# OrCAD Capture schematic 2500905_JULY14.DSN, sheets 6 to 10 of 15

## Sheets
6 PAGE10: size Custom
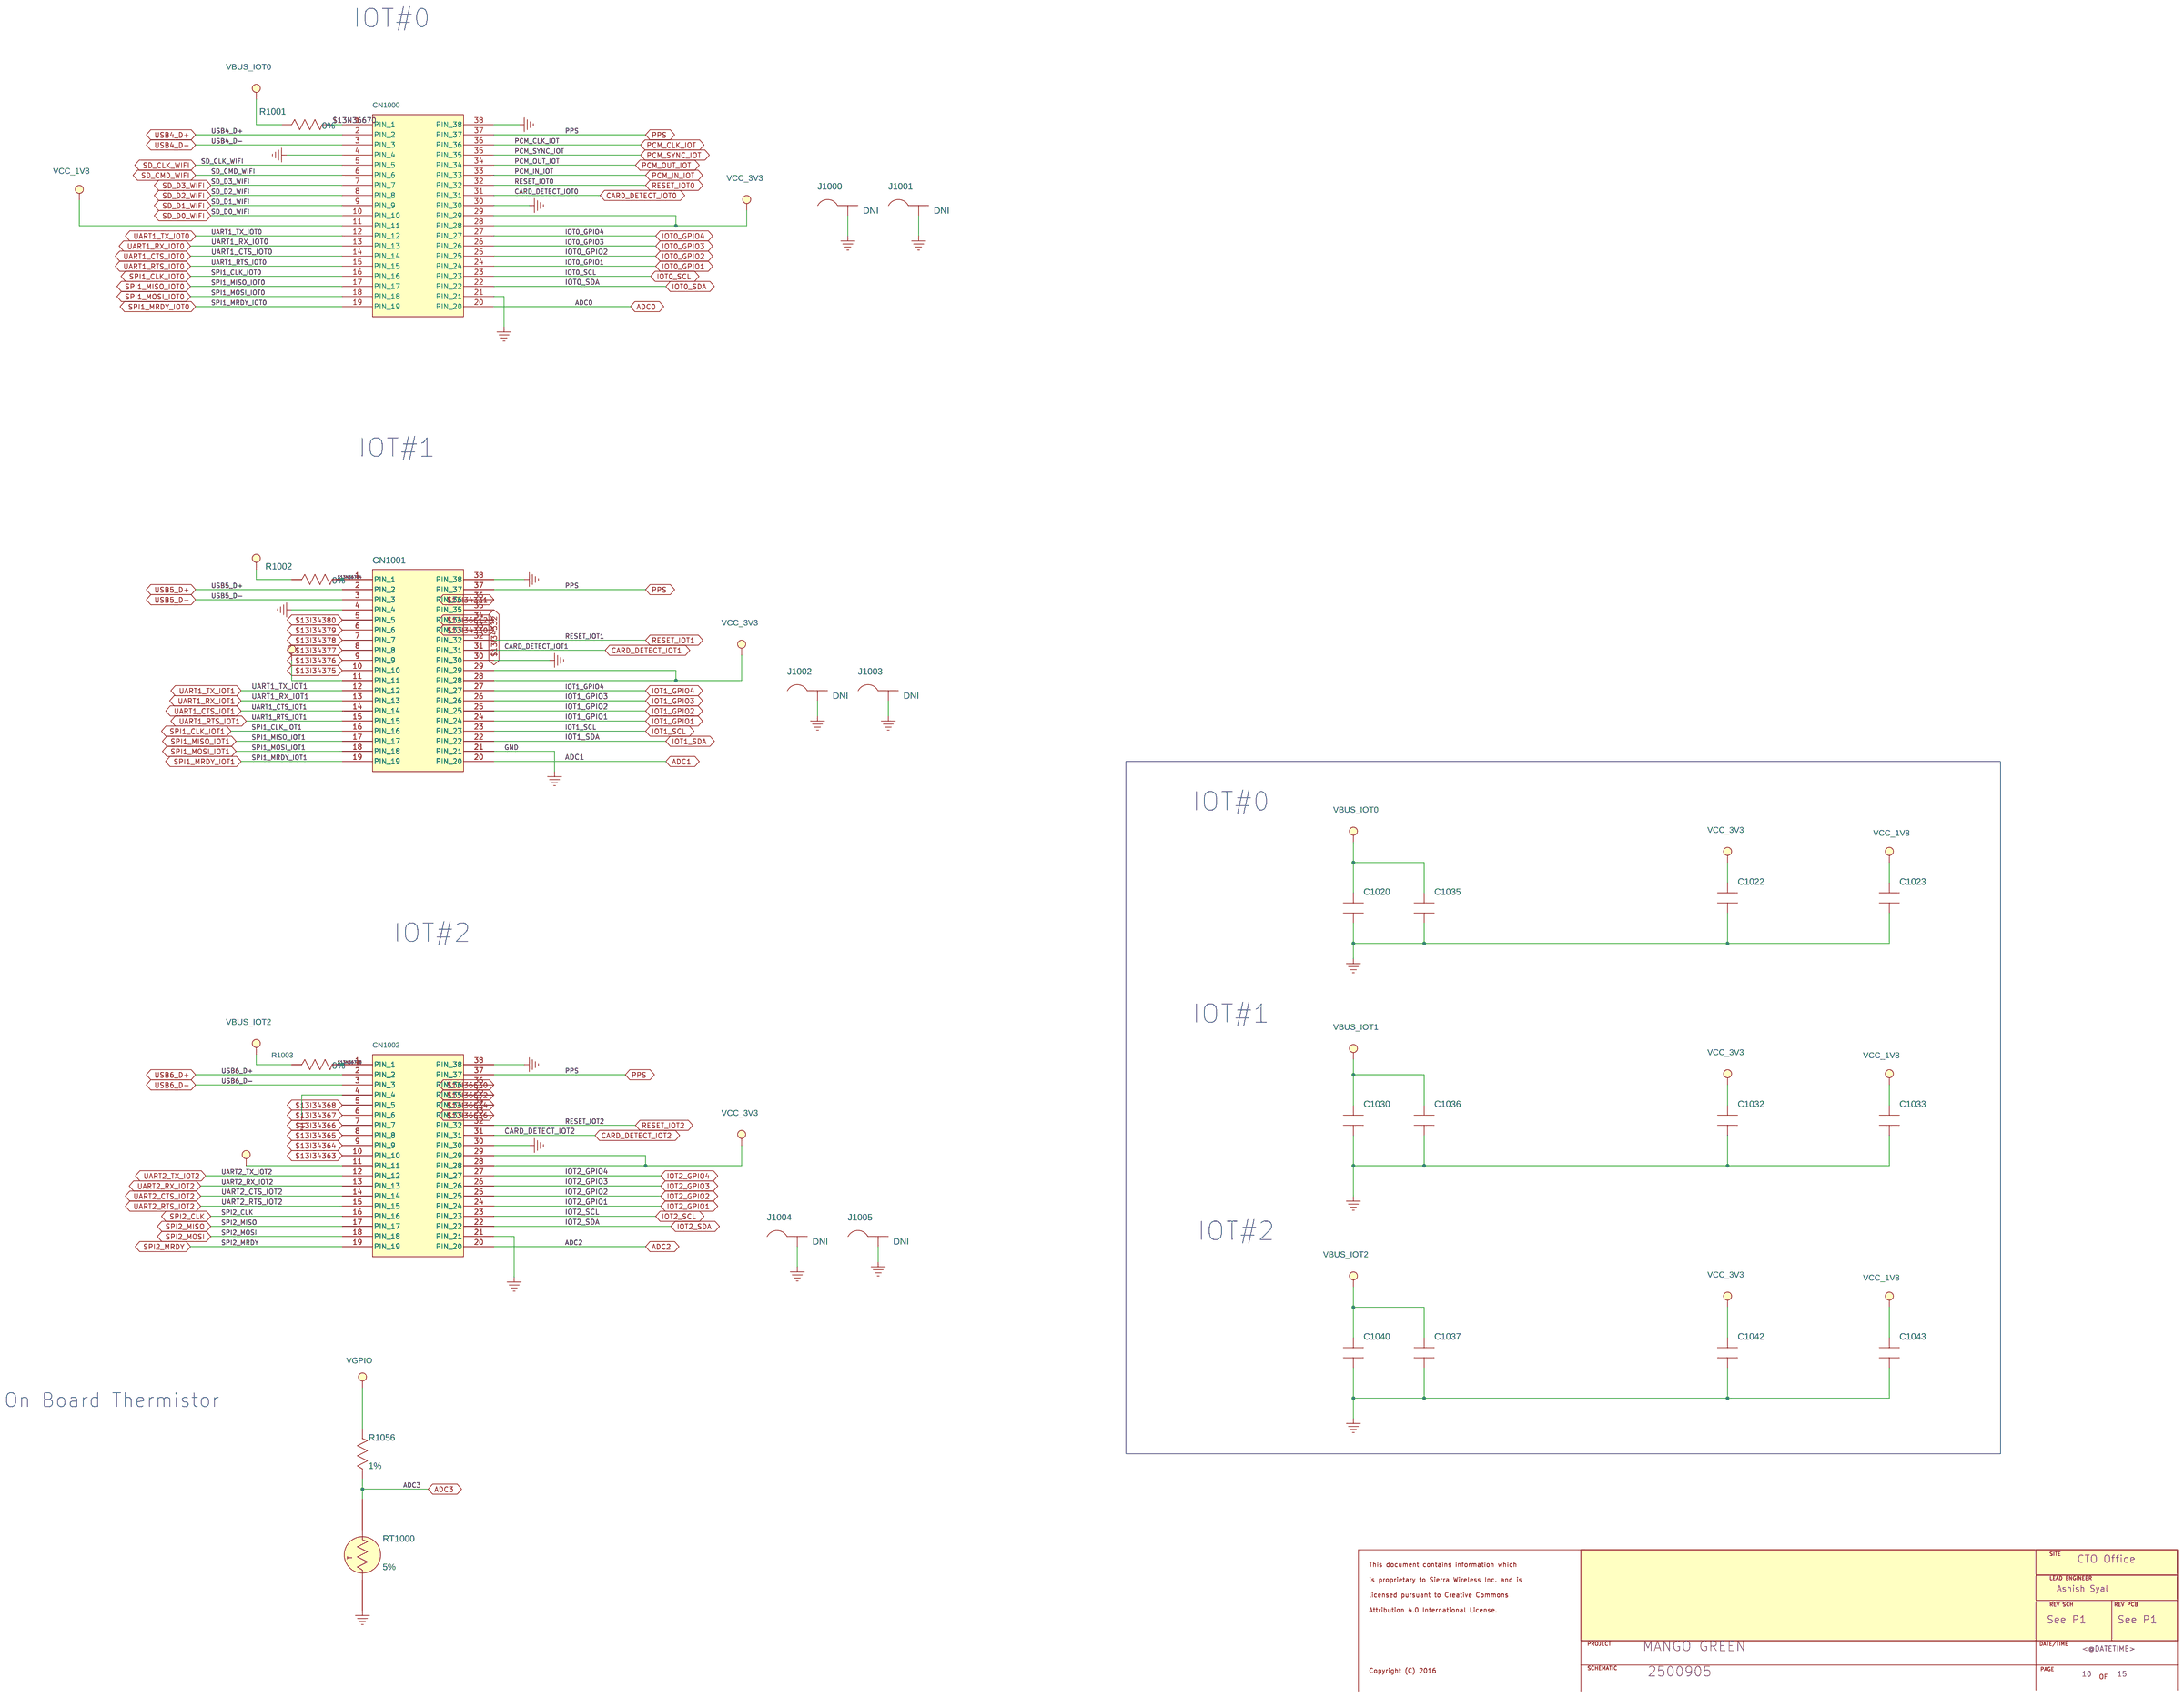
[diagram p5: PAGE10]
7 PAGE9: size Custom
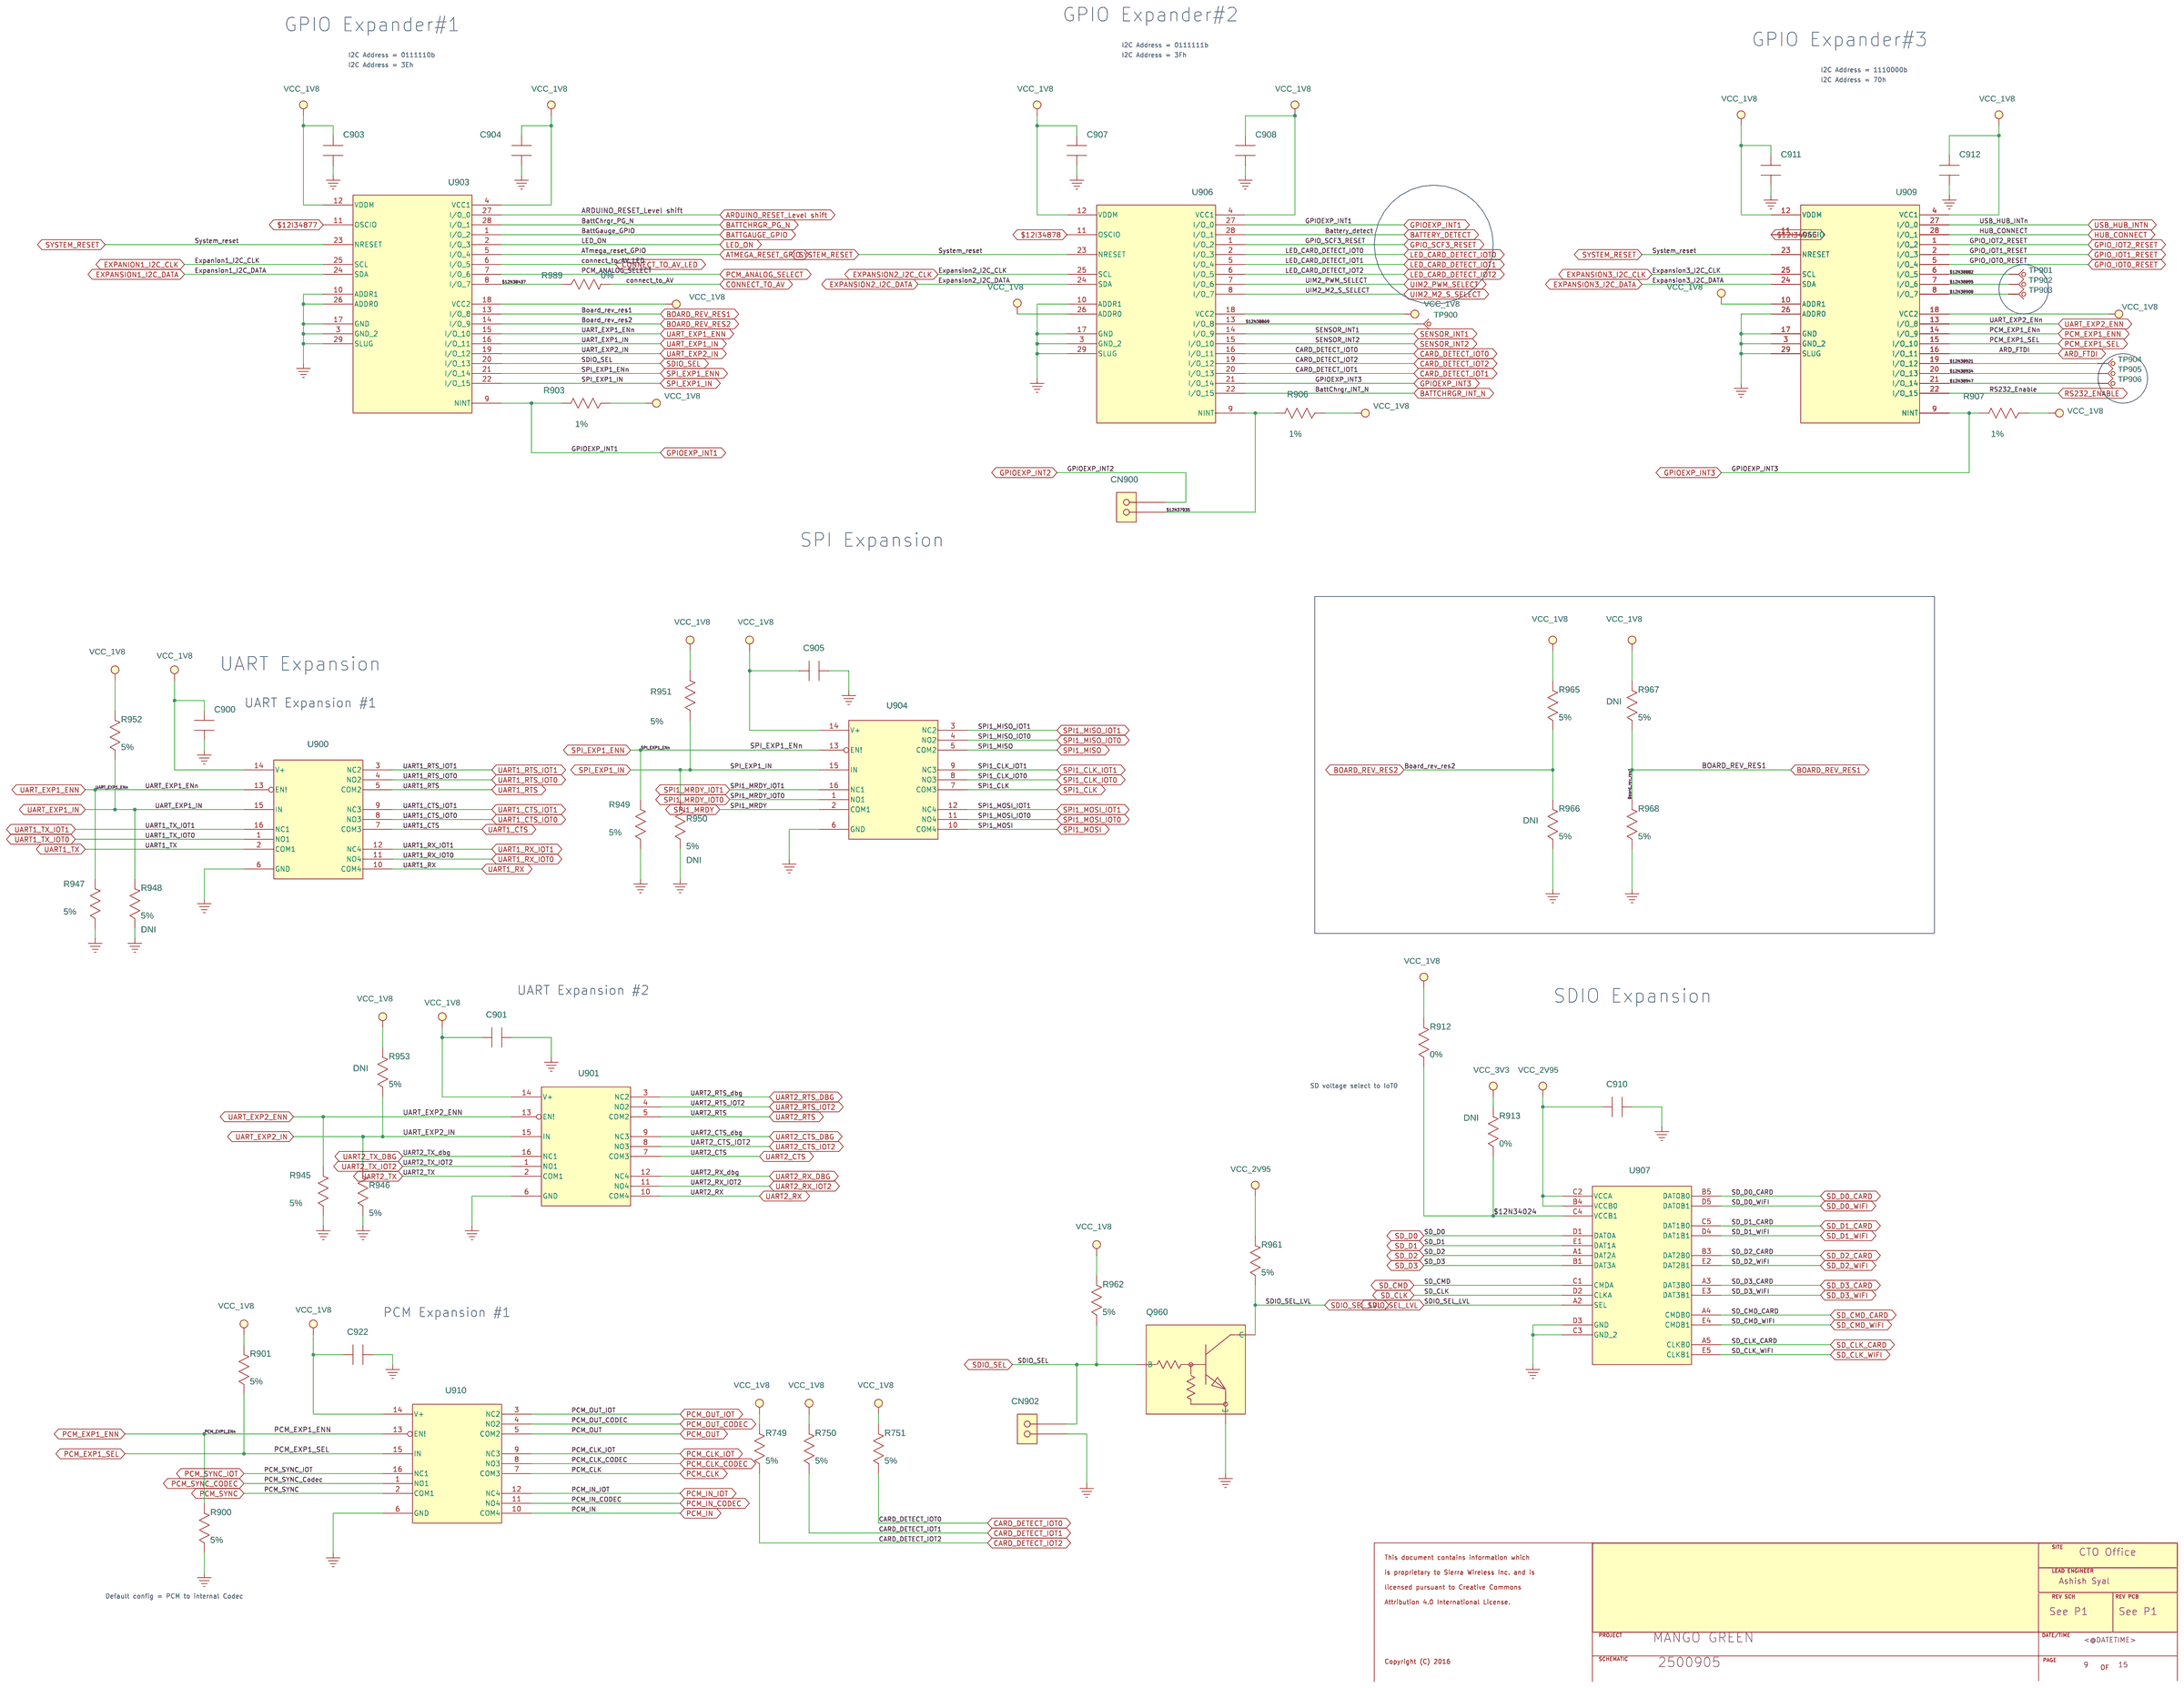
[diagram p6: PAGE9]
8 PAGE8: size Custom
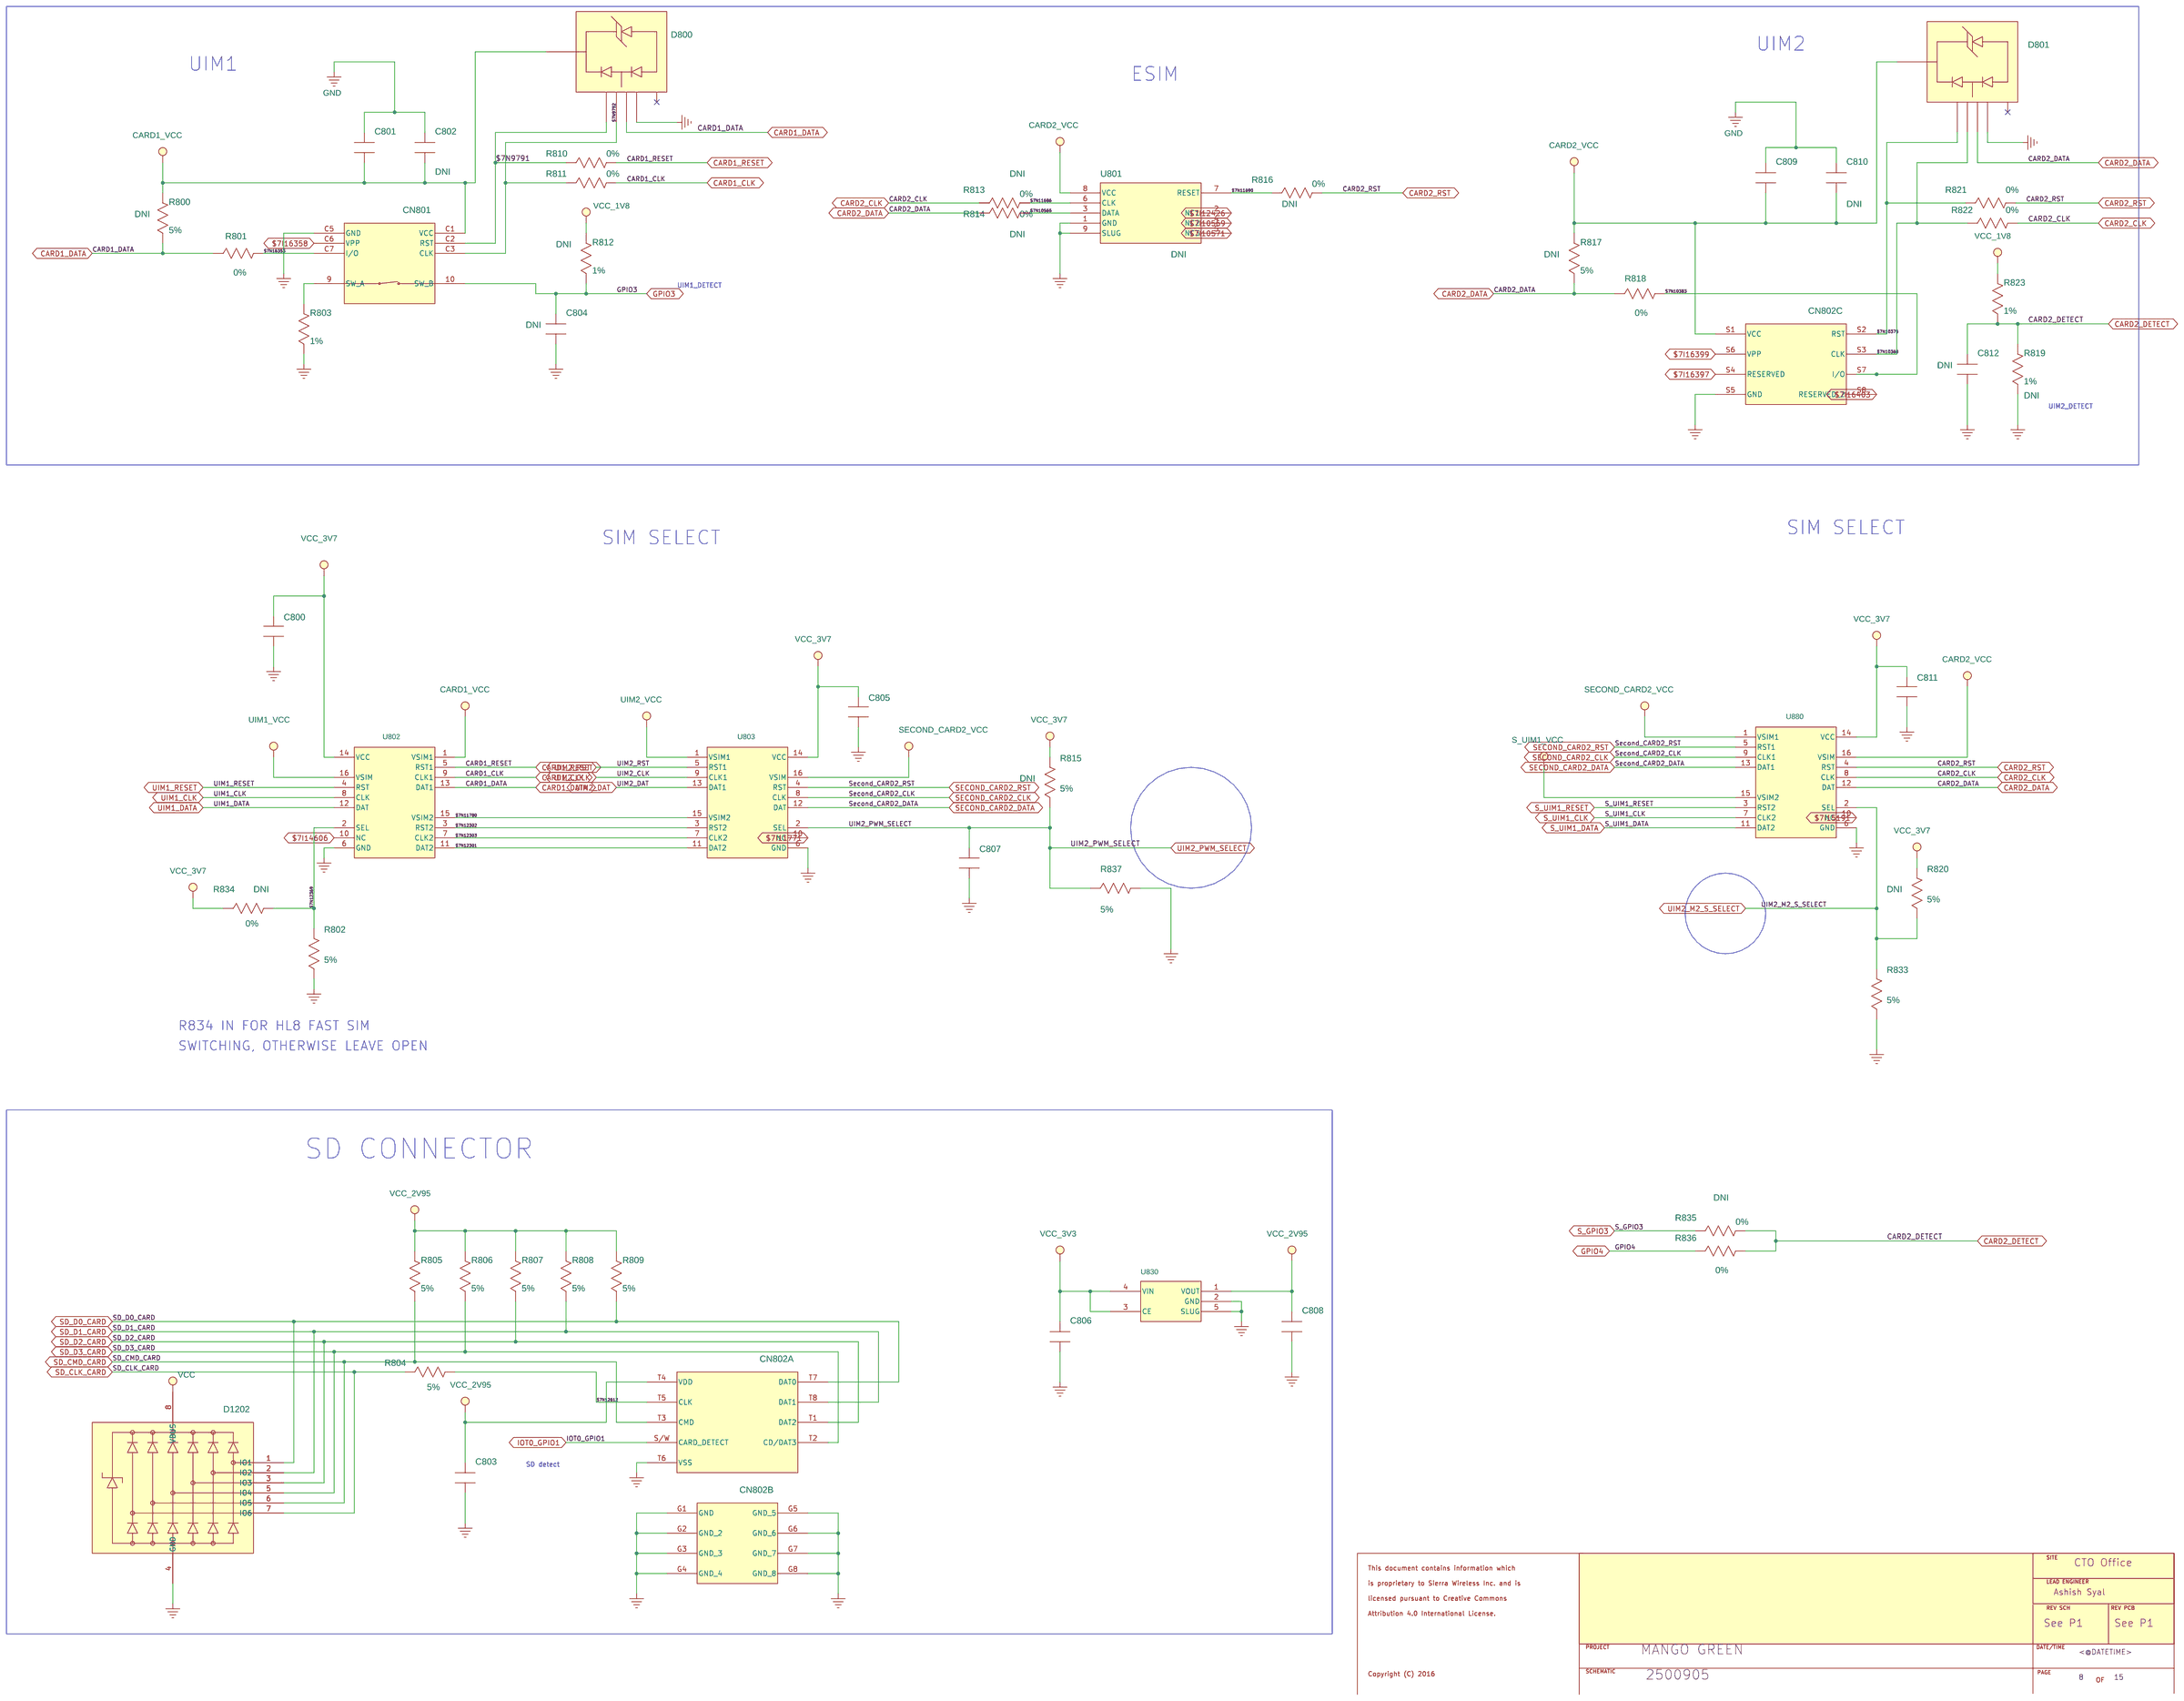
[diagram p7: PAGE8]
9 PAGE7: size Custom
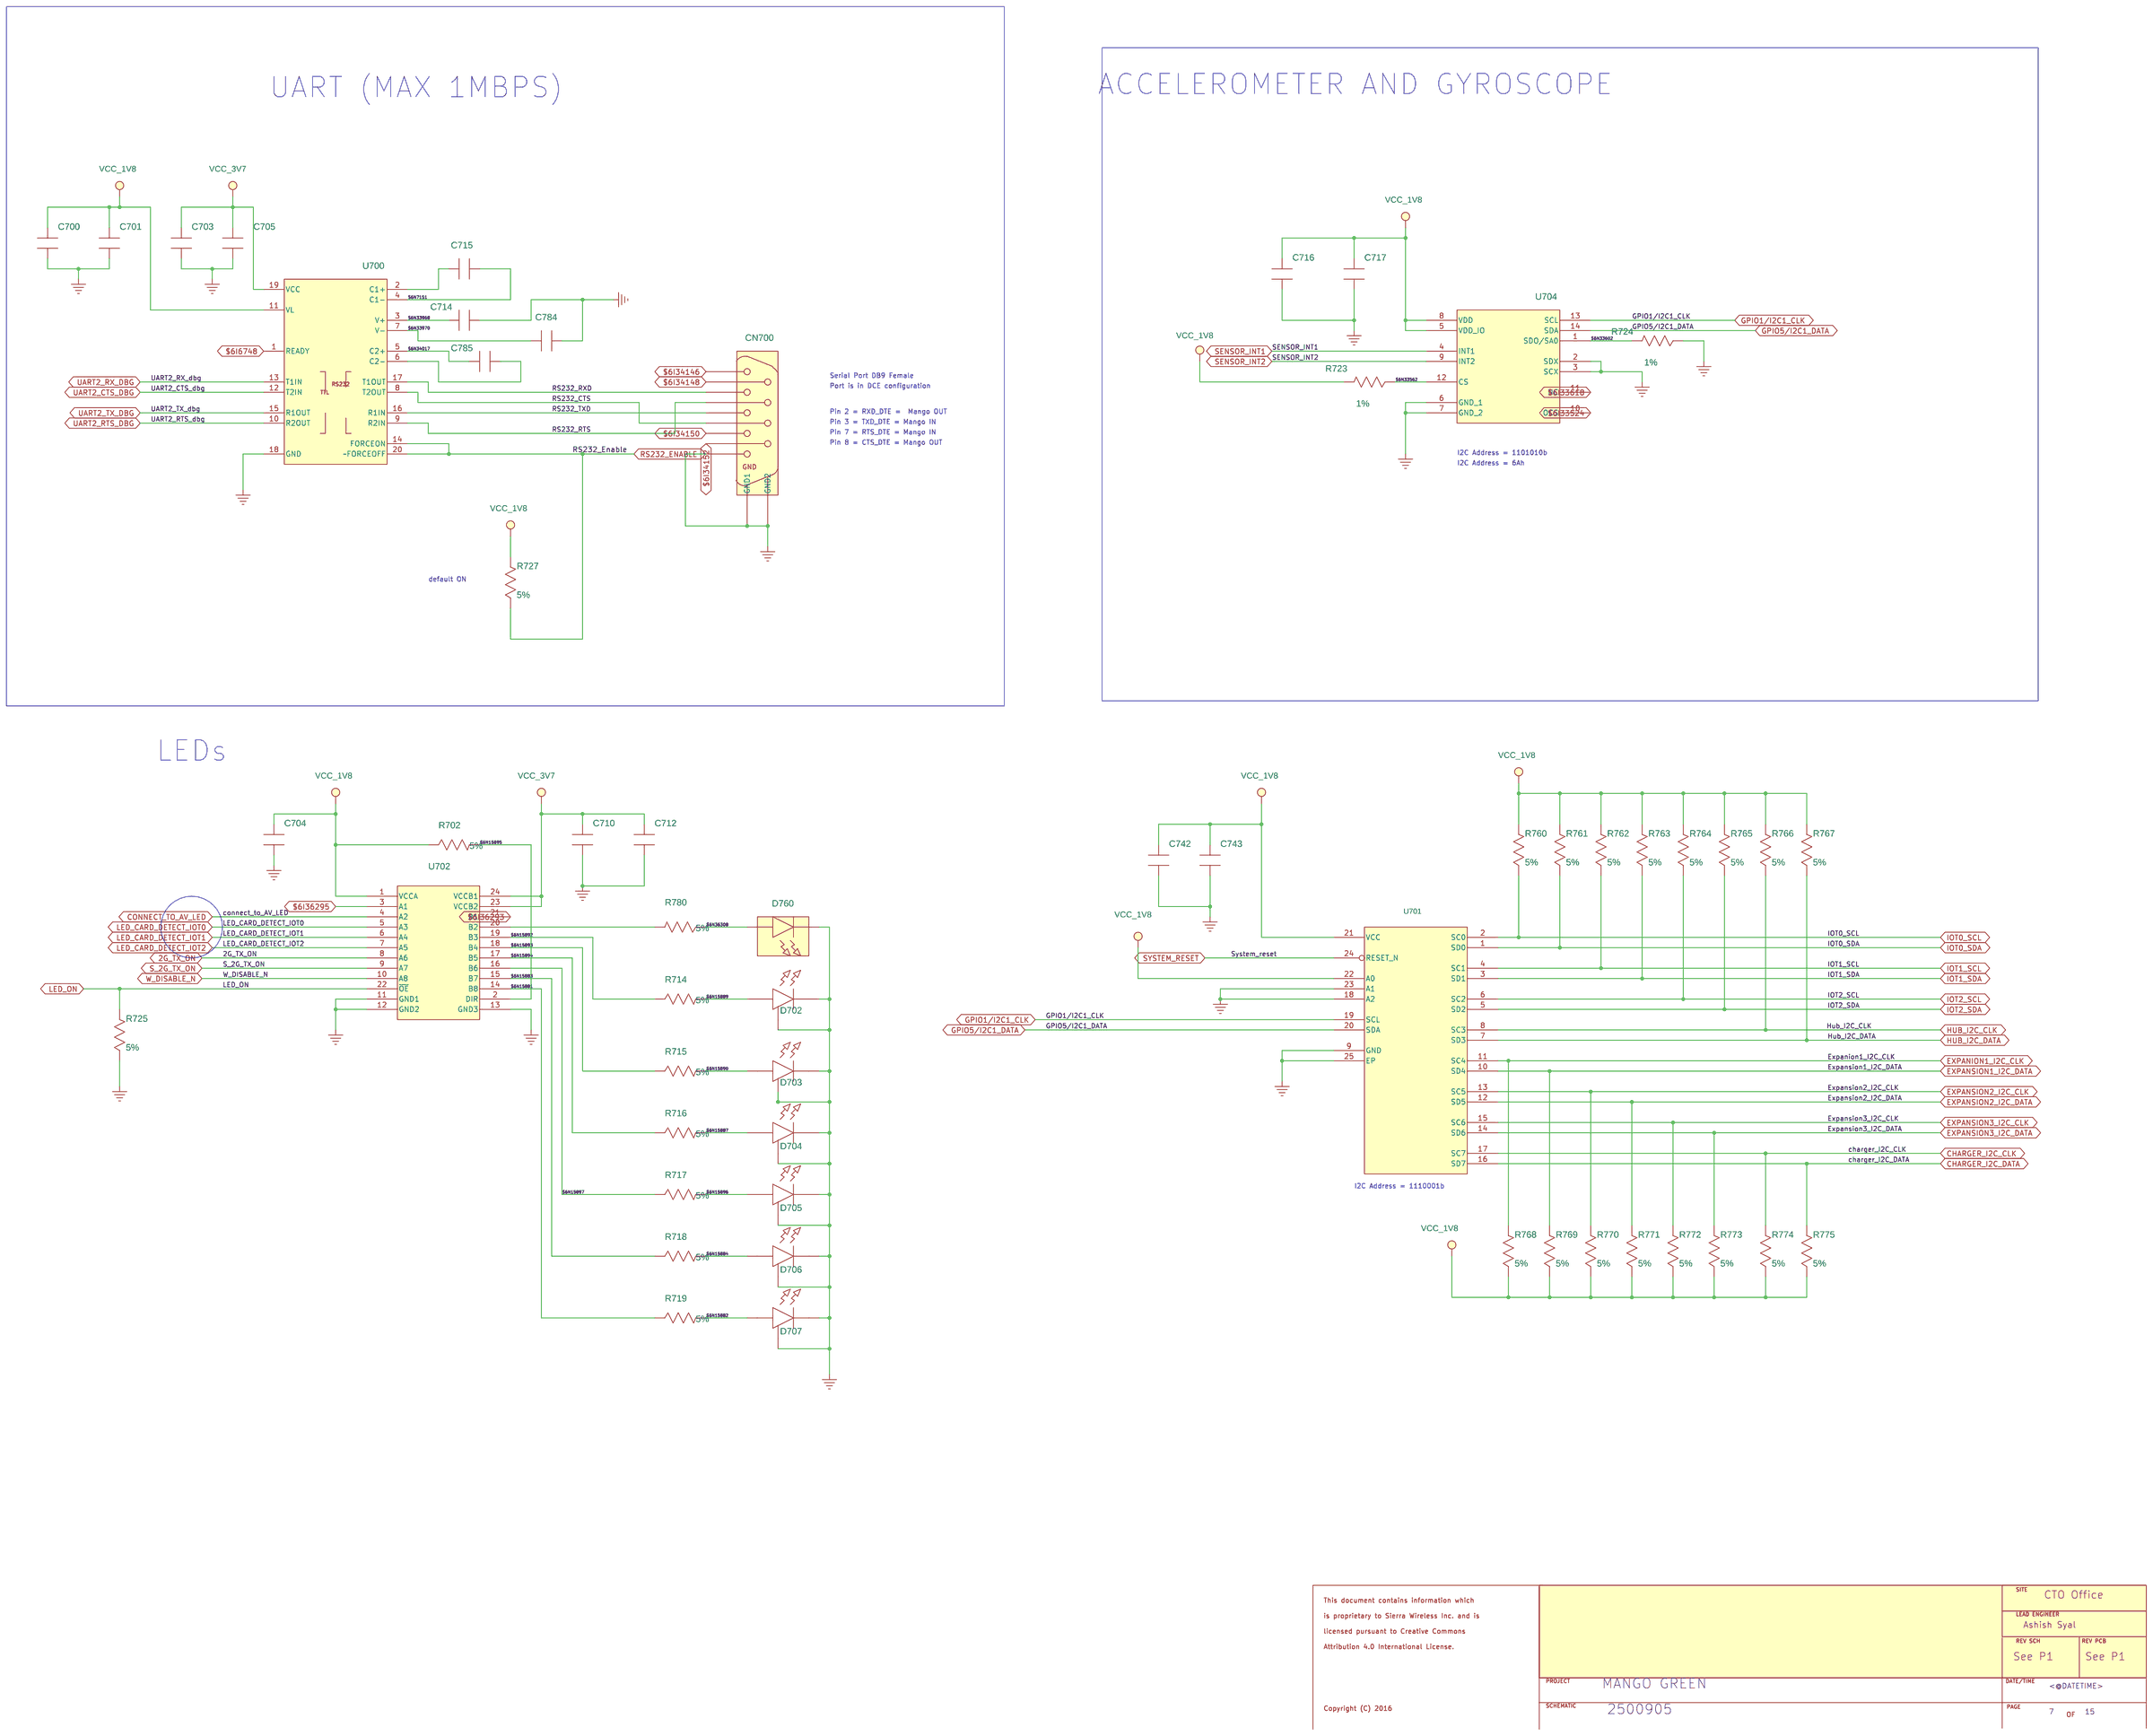
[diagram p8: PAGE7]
10 PAGE6: size Custom
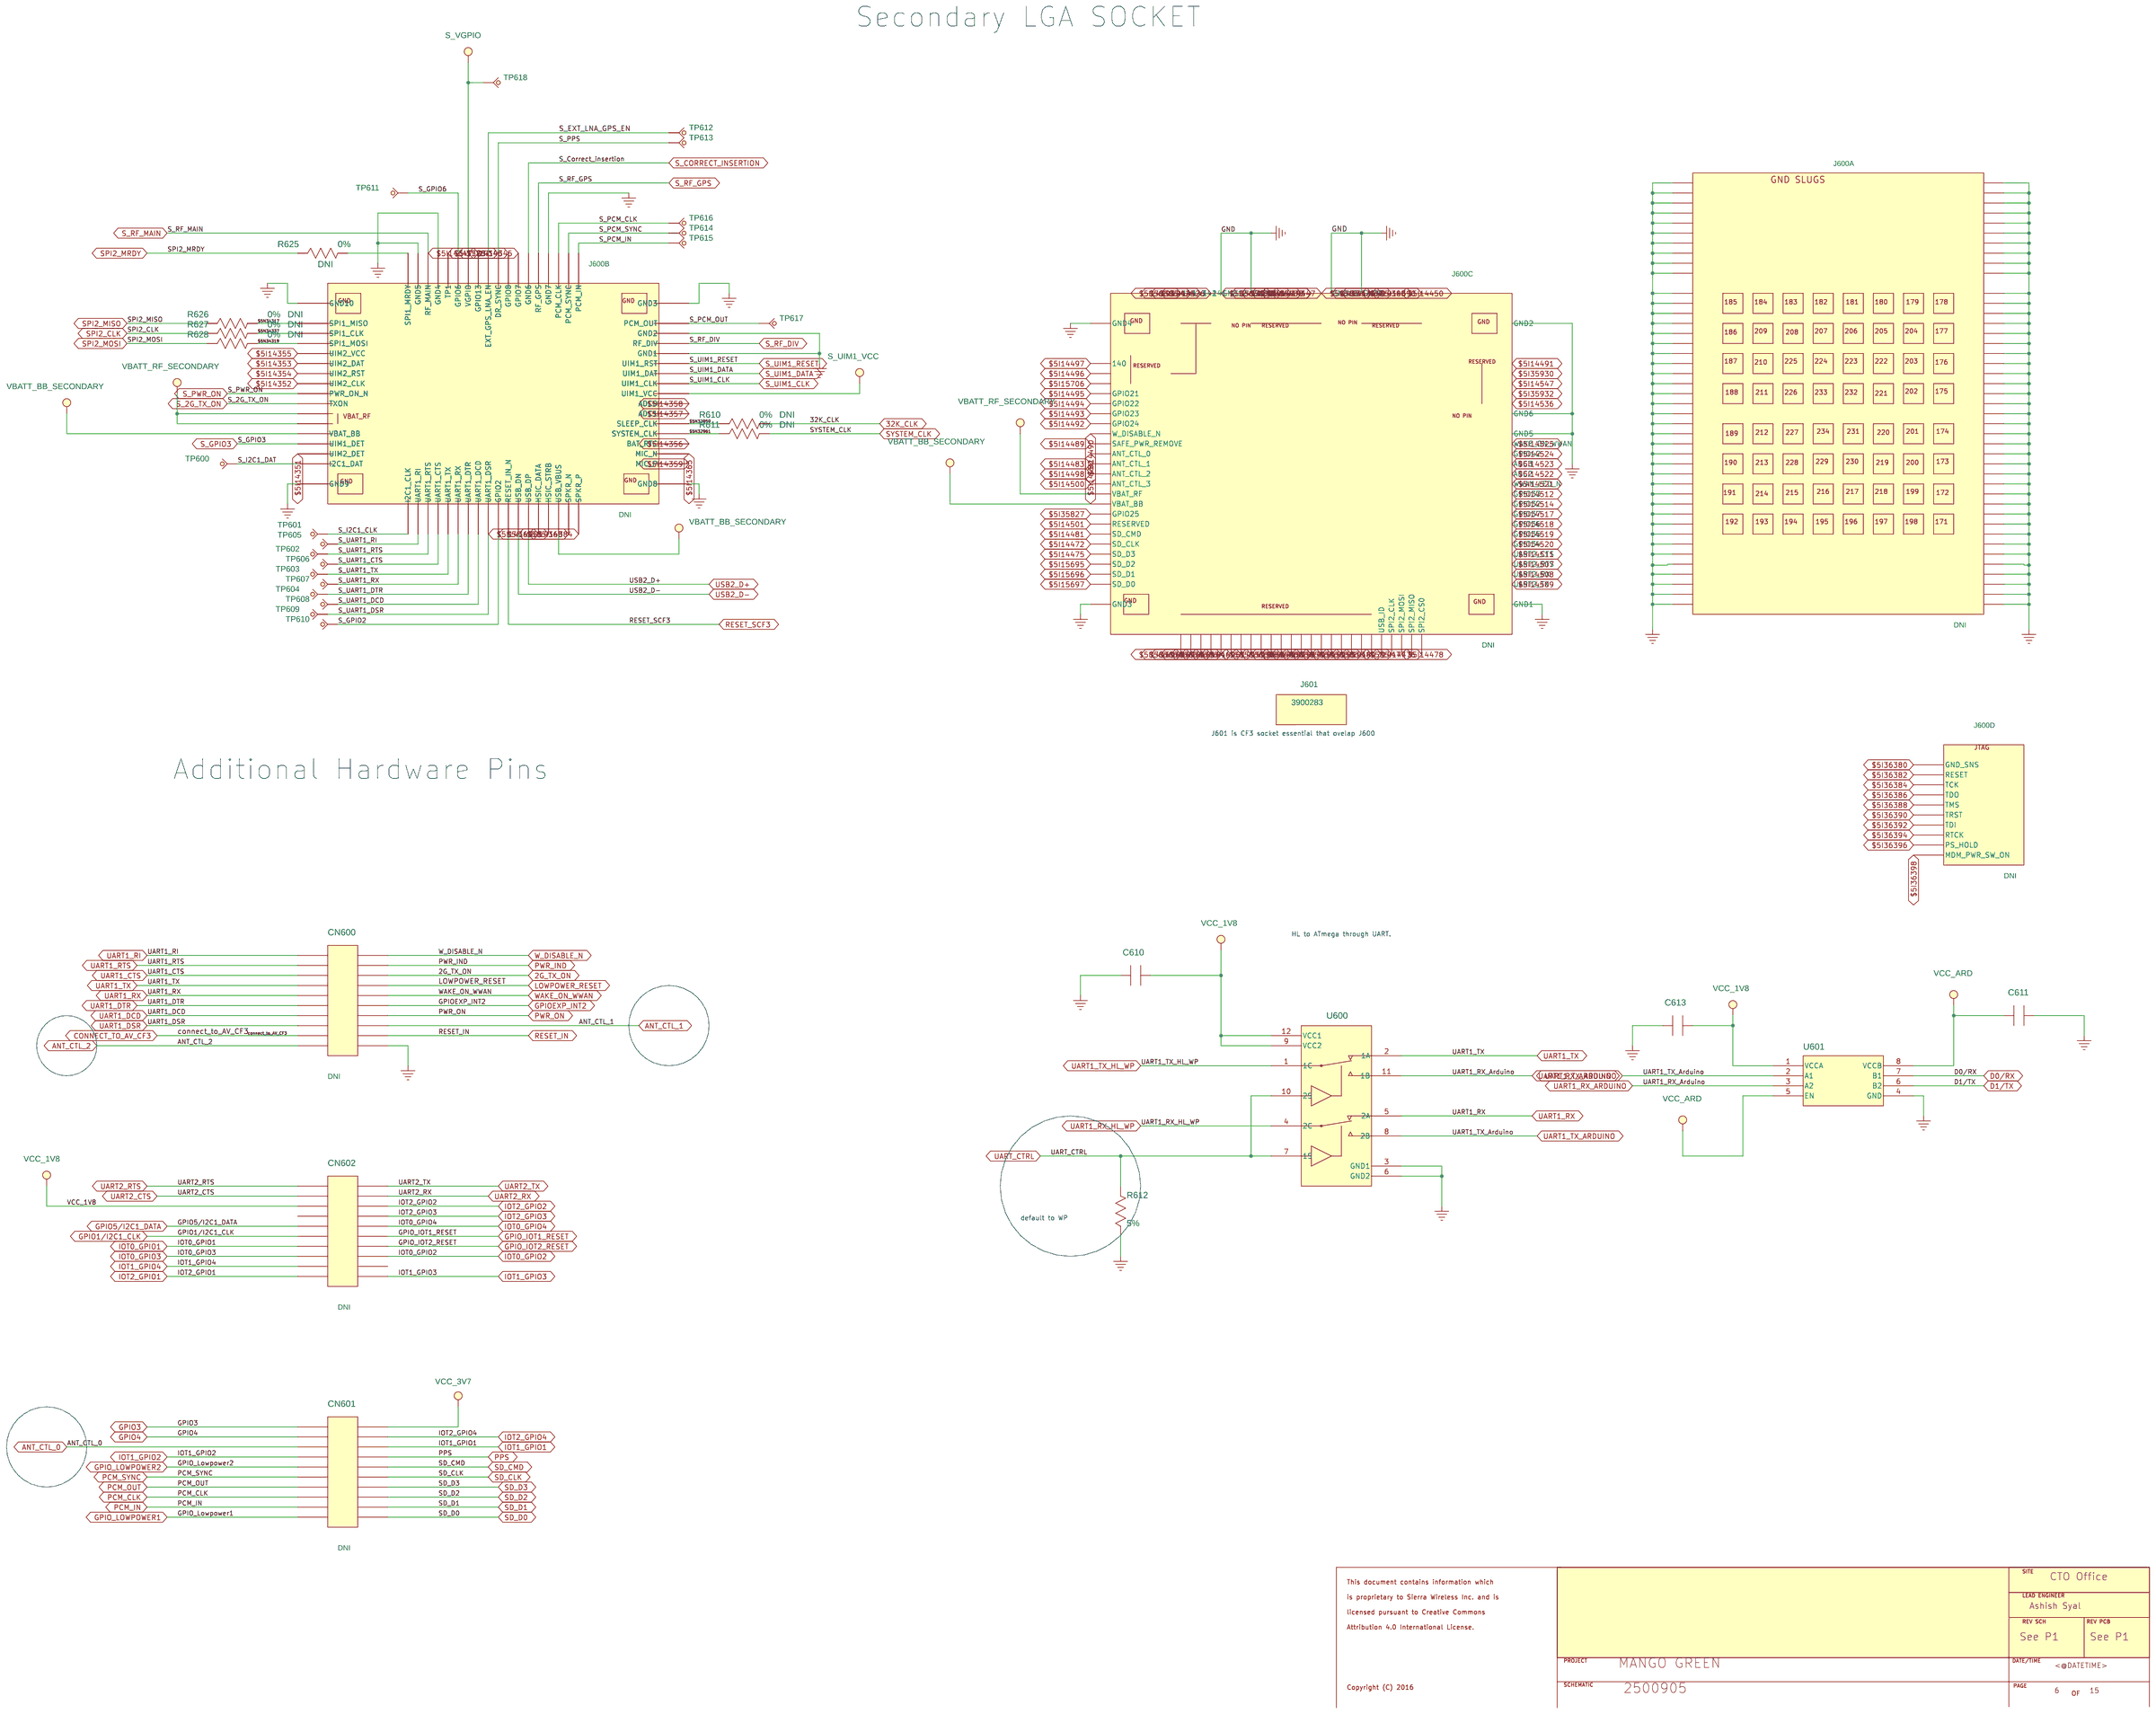
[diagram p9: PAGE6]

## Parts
sheet PAGE6
6  C_OPEN_HW  [TP]
C610  100nF  [0402C]
C611  100nF  [0402C]
C613  100nF  [0402C]
CN600  SFMC-110-02-L-D-TR  [CONN_20P_1308x0305_0127CC_SMT]
CN601  SFMC-110-02-L-D-TR  [CONN_20P_1308x0305_0127CC_SMT]
CN602  SFMC-110-02-L-D-TR  [CONN_20P_1308x0305_0127CC_SMT]
J600  MULTI_SYMBOL_SOCKET_LGA-244  [LGA_244P_CF3_2650x2550_SNAP_IN_SOCKET_SMK]  (sections A,B,C,D)
J601  -  [LGA_0P_CF3]
R610  0  [0402R]
R611  0  [0402R]
R612  10K  [0402R]
R625  0  [0402R]
R626  0  [0402R]
R627  0  [0402R]
R628  0  [0402R]
TP600  TESTPOINT_0100_RND  [TP_0100_RND_NP]
TP601  TESTPOINT_0100_RND  [TP_0100_RND_NP]
TP602  TESTPOINT_0100_RND  [TP_0100_RND_NP]
TP603  TESTPOINT_0100_RND  [TP_0100_RND_NP]
TP604  TESTPOINT_0100_RND  [TP_0100_RND_NP]
TP605  TESTPOINT_0100_RND  [TP_0100_RND_NP]
TP606  TESTPOINT_0100_RND  [TP_0100_RND_NP]
TP607  TESTPOINT_0100_RND  [TP_0100_RND_NP]
TP608  TESTPOINT_0100_RND  [TP_0100_RND_NP]
TP609  TESTPOINT_0100_RND  [TP_0100_RND_NP]
TP610  TESTPOINT_0100_RND  [TP_0100_RND_NP]
TP611  TESTPOINT_0100_RND  [TP_0100_RND_NP]
TP612  TESTPOINT_0100_RND  [TP_0100_RND_NP]
TP613  TESTPOINT_0100_RND  [TP_0100_RND_NP]
TP614  TESTPOINT_0100_RND  [TP_0100_RND_NP]
TP615  TESTPOINT_0100_RND  [TP_0100_RND_NP]
TP616  TESTPOINT_0100_RND  [TP_0100_RND_NP]
TP617  TESTPOINT_0100_RND  [TP_0100_RND_NP]
TP618  TESTPOINT_0100_RND  [TP_0100_RND_NP]
U600  NLAS3158MNR2G  [DFN_12P_0300x0100_0050CC]
U601  PI4ULS5V202XVE  [DFN_8P_0160x0120_0040CC]
sheet PAGE7
7  C_OPEN_HW  [TP]
C700  10nF  [0402C]
C701  100nF  [0402C]
C703  100nF  [0402C]
C704  100nF  [0402C]
C705  10nF  [0402C]
C710  100nF  [0402C]
C712  100nF  [0402C]
C714  1uF  [0402C]
C715  1uF  [0402C]
C716  100nF  [0402C]
C717  100nF  [0402C]
C742  100nF  [0402C]
C743  100nF  [0402C]
C784  1uF  [0402C]
C785  1uF  [0402C]
CN700  DSUB  [CONN_9P_3080x1060_DSUB_REC_RA_AMPHENOL_SD]
D702  LED GREEN  [LED_3P_0300x0200_RA]
D703  LED GREEN  [LED_3P_0300x0200_RA]
D704  LED GREEN  [LED_3P_0300x0200_RA]
D705  LED GREEN  [LED_3P_0300x0200_RA]
D706  LED GREEN  [LED_3P_0300x0200_RA]
D707  LED GREEN  [LED_3P_0300x0200_RA]
D760  LED GREEN  [0603D]
R702  10K  [0402R]
R714  1.5K  [0402R]
R715  1.5K  [0402R]
R716  1.5K  [0402R]
R717  1.5K  [0402R]
R718  1.5K  [0402R]
R719  1.5K  [0402R]
R723  10K  [0402R]
R724  10K  [0402R]
R725  47K  [0402R]
R727  47K  [0402R]
R760  2.2K  [0402R]
R761  2.2K  [0402R]
R762  2.2K  [0402R]
R763  2.2K  [0402R]
R764  2.2K  [0402R]
R765  2.2K  [0402R]
R766  2.2K  [0402R]
R767  2.2K  [0402R]
R768  2.2K  [0402R]
R769  2.2K  [0402R]
R770  2.2K  [0402R]
R771  2.2K  [0402R]
R772  2.2K  [0402R]
R773  2.2K  [0402R]
R774  2.2K  [0402R]
R775  2.2K  [0402R]
R780  300  [0402R]
U700  RS232_MAX13235EEUP  [TSSOP_20P_0650x0440_0065CC]
U701  TCA9548ARGER  [QFN_24P_0400x0400_SLUG_0210x0210_0050CC]
U702  SN74LVC8T245PWR  [TSSOP_24P_0780x0440_0065CC]
U704  LSM6DS3  [QFN_14P_0250x0300_0050CC]
sheet PAGE8
8  C_OPEN_HW  [TP]
C800  100nF  [0402C]
C801  100nF  [0402C]
C802  4.7uF  [0603C]
C803  100nF  [0402C]
C804  1nF  [0402C]
C805  100nF  [0402C]
C806  1uF  [0402C]
C807  22pF  [0402C]
C808  1uF  [0402C]
C809  100nF  [0402C]
C810  4.7uF  [0603C]
C811  100nF  [0402C]
C812  1nF  [0402C]
CN801  CN_6P_SIM_2P_NC_SWITCH  [CONN_6P_1585x1650_SWITCH_SIM]
CN802  MULTI_SYMBOL_104168-1620_USD  [CONN_25P_1780x1290_0088CC_MICROSDSIM]  (sections A,B,C)
D800  0.5pF  [DFN_6P_0145x0100_0050CC]
D801  0.5pF  [DFN_6P_0145x0100_0050CC]
D1202  1.6pF  [QFN_8P_0150x0150_0050CC]
R800  15K  [0402R]
R801  0  [0402R]
R802  10K  [0402R]
R803  1K  [0402R]
R804  33  [0402R]
R805  47K  [0402R]
R806  47K  [0402R]
R807  47K  [0402R]
R808  47K  [0402R]
R809  47K  [0402R]
R810  0  [0402R]
R811  0  [0402R]
R812  100K  [0402R]
R813  0  [0402R]
R814  0  [0402R]
R815  10K  [0402R]
R816  0  [0402R]
R817  15K  [0402R]
R818  0  [0402R]
R819  1K  [0402R]
R820  10K  [0402R]
R821  0  [0402R]
R822  0  [0402R]
R823  100K  [0402R]
R833  10K  [0402R]
R834  0  [0402R]
R835  0  [0402R]
R836  0  [0402R]
R837  10K  [0402R]
U801  eSIM MODULE  [DFN_8P_0500x0600_SLUG_0420x0340_0127CC_ESIM_MODULE_MFF2]
U802  IC_16P_4PDT_FSA2567  [QFN_16P_0260x0180_040CC]
U803  IC_16P_4PDT_FSA2567  [QFN_16P_0260x0180_040CC]
U830  IC_5P_LDO_XC6223  [DFN_4P_0100x0100_SLUG_ROTATED_45DEG_0042x0042_0065CC]
U880  IC_16P_4PDT_FSA2567  [QFN_16P_0260x0180_040CC]
sheet PAGE9
9  C_OPEN_HW  [TP]
C900  100nF  [0402C]
C901  100nF  [0402C]
C903  100nF  [0402C]
C904  100nF  [0402C]
C905  100nF  [0402C]
C907  100nF  [0402C]
C908  100nF  [0402C]
C910  100nF  [0402C]
C911  100nF  [0402C]
C912  100nF  [0402C]
C922  100nF  [0402C]
CN900  POST TERMINAL STRIP  [CONN_2P_0508x0254_VERTICAL_HEADER_SINGLE_ROW_THRU_SAMTEC_TSW]
CN902  POST TERMINAL STRIP  [CONN_2P_0508x0254_VERTICAL_HEADER_SINGLE_ROW_THRU_SAMTEC_TSW]
Q960  NPN_PDTC115EM  [DFN_3P_0060x0100_0035CC]
R749  47K  [0402R]
R750  47K  [0402R]
R751  47K  [0402R]
R900  10K  [0402R]
R901  10K  [0402R]
R903  10K  [0402R]
R906  10K  [0402R]
R907  10K  [0402R]
R912  0  [0402R]
R913  0  [0402R]
R945  47K  [0402R]
R946  47K  [0402R]
R947  47K  [0402R]
R948  47K  [0402R]
R949  47K  [0402R]
R950  47K  [0402R]
R951  47K  [0402R]
R952  47K  [0402R]
R953  47K  [0402R]
R961  10K  [0402R]
R962  10K  [0402R]
R965  47K  [0402R]
R966  47K  [0402R]
R967  47K  [0402R]
R968  47K  [0402R]
R989  0  [0402R]
TP900  TESTPOINT_0100_RND  [TP_0100_RND_NP]
TP901  TESTPOINT_0100_RND  [TP_0100_RND_NP]
TP902  TESTPOINT_0100_RND  [TP_0100_RND_NP]
TP903  TESTPOINT_0100_RND  [TP_0100_RND_NP]
TP904  TESTPOINT_0100_RND  [TP_0100_RND_NP]
TP905  TESTPOINT_0100_RND  [TP_0100_RND_NP]
TP906  TESTPOINT_0100_RND  [TP_0100_RND_NP]
U900  TS3A5018RSVR  [QFN_16P_0260x0180_0040CC]
U901  TS3A5018RSVR  [QFN_16P_0260x0180_0040CC]
U903  SX1509IULTRTR  [QFN_28P_0400x0400_SLUG_0265x0265_0040CC]
U904  TS3A5018RSVR  [QFN_16P_0260x0180_0040CC]
U906  SX1509IULTRTR  [QFN_28P_0400x0400_SLUG_0265x0265_0040CC]
U907  TXS02612ZQSR  [BGA_24P_0300x0300_0050CC_0030PD]
U909  SX1509IULTRTR  [QFN_28P_0400x0400_SLUG_0265x0265_0040CC]
U910  TS3A5018RSVR  [QFN_16P_0260x0180_0040CC]
sheet PAGE10
10  C_OPEN_HW  [TP]
C1020  4.7uF  [0603C]
C1022  10uF  [0603C]
C1023  10uF  [0603C]
C1030  4.7uF  [0603C]
C1032  10uF  [0603C]
C1033  10uF  [0603C]
C1035  47uF  [1206C]
C1036  47uF  [1206C]
C1037  47uF  [1206C]
C1040  4.7uF  [0603C]
C1042  10uF  [0603C]
C1043  10uF  [0603C]
CN1000  2110819-1  [CONN_38P_1820x1150_0080CC_EVERCLEAR]
CN1001  2110819-1  [CONN_38P_1820x1150_0080CC_EVERCLEAR]
CN1002  2110819-1  [CONN_38P_1820x1150_0080CC_EVERCLEAR]
J1000  RF_CLIP  [CONN_1P_0490x0110_SPRING_CLIP]
J1001  RF_CLIP  [CONN_1P_0490x0110_SPRING_CLIP]
J1002  RF_CLIP  [CONN_1P_0490x0110_SPRING_CLIP]
J1003  RF_CLIP  [CONN_1P_0490x0110_SPRING_CLIP]
J1004  RF_CLIP  [CONN_1P_0490x0110_SPRING_CLIP]
J1005  RF_CLIP  [CONN_1P_0490x0110_SPRING_CLIP]
R1001  0  [0402R]
R1002  0  [0402R]
R1003  0  [0402R]
R1056  62K  [0402R]
RT1000  220K  [0402R]

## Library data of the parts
6-10 = Sierra_Title_Block_0: @DATETIME: <@DATETIME>; @Name: 2500905; @SheetTotal: 15; AUTHOR: Ashish Syal; PROJECT: MANGO GREEN; REVISION_PCB: See P1; REVISION_SCH: See P1; SITE: CTO Office
C610 C611 C613 C701 C703 C704 C710 C712 C800 C801 C803 C805 C809 C811 C900 C901 C903-C905 C907 C908 C910-C912 C922 = CAP_NMC0402X7R104K16TRPF: ASSEMBLY: <ASSEMBLY>; Variant Variable Text: <Variant Variable Text>
CN600-CN602 = CN_20P_DUAL_ROW_Z_NO_BUBBLES: ASSEMBLY: <ASSEMBLY>; Variant Variable Text: DNI
J600 = MULTI_SYMBOL_SOCKET_LGA-244: ASSEMBLY: <ASSEMBLY>; Variant Variable Text: DNI
J601 = DUMMY_SYMBOL_2: CONN, SNAP IN SOCKET FRAME, for ESSENTIAL MODULES, 26.5x25.5x5.1mm; Arena Link: https://app.bom.com/a/P7Q8RBUBUDDXUOF2?v=files.associations; CATEGORY: Connector; Commodity Class: EM - Electro Mechanical; Created Date: 2015-02-10T17:56:07-08:00; DEVICE: 3900283; DXDB_LIBNAME: Connector; Effective Date: 2015-03-04T09:20:38-08:00; Halogen Free: N/A; Part Height: 5.1mm; Part Status: Production; REVISION: 1; RoHS Compliant: N/A
R610 R611 R625-R628 R813 R814 R816 R834 R835 R913 = RES_RK73Z1ETTP: ASSEMBLY: <ASSEMBLY>; TOLERANCE: 0%; Variant Variable Text: DNI
R612 R702 R802 R833 R837 R900 R901 R961 R962 = RES_MCR01MZPJ103: ASSEMBLY: <ASSEMBLY>; TOLERANCE: 5%; Variant Variable Text: <Variant Variable Text>
TP600-TP618 TP900-TP906 = TESTPOINT: TEST POINT, ROUND, 1mm DIAMETER; CATEGORY: Layout Feature; DXDB_LIBNAME: Layout_Feature; OWNER: Michael Sorensen; Part Height: 0.01mm; REQUESTOR: Michael Sorensen
U600 = IC_12P_SPDT_NLAS3158MNR2G: ASSEMBLY: <ASSEMBLY>; Variant Variable Text: <Variant Variable Text>
U601 = IC_8P_2-BIT_PI4ULS5V202XVE: ASSEMBLY: <ASSEMBLY>; Variant Variable Text: <Variant Variable Text>
C700 C705 = CAP_GRM155R71E103KA01D: ASSEMBLY: <ASSEMBLY>; Variant Variable Text: <Variant Variable Text>
C714 C715 C784 C785 C806 C808 = CAP_GRM155R61A105KE15D: ASSEMBLY: <ASSEMBLY>; Variant Variable Text: <Variant Variable Text>
C716 C717 C742 C743 = CAP_GRM155R61A104KA01D: ASSEMBLY: <ASSEMBLY>; Variant Variable Text: <Variant Variable Text>
CN700 = CN_9P_DSUB_2P_GND: ASSEMBLY: <ASSEMBLY>; Variant Variable Text: <Variant Variable Text>
D702-D707 = LED_3P: ASSEMBLY: <ASSEMBLY>; Variant Variable Text: <Variant Variable Text>
D760 = LED: ASSEMBLY: <ASSEMBLY>; Variant Variable Text: <Variant Variable Text>
R714-R719 = RES_RK73B1ETTP152J: ASSEMBLY: <ASSEMBLY>; TOLERANCE: 5%; Variant Variable Text: <Variant Variable Text>
R723 R724 R903 R906 R907 = RES_MCR01MZPF1002: ASSEMBLY: <ASSEMBLY>; TOLERANCE: 1%; Variant Variable Text: <Variant Variable Text>
R725 R727 R749-R751 R805-R809 R945-R947 R949 R951 R952 R965 R968 = RES_MCR01MZPJ473: ASSEMBLY: <ASSEMBLY>; TOLERANCE: 5%; Variant Variable Text: <Variant Variable Text>
R760-R775 = RES_MCR01MZPJ222: ASSEMBLY: <ASSEMBLY>; TOLERANCE: 5%; Variant Variable Text: <Variant Variable Text>
R780 = RES_RK73B1ETTP301J: ASSEMBLY: <ASSEMBLY>; TOLERANCE: 5%; Variant Variable Text: <Variant Variable Text>
U700 = IC_20P_RS232_MAX13235EEUP: ASSEMBLY: <ASSEMBLY>; Variant Variable Text: <Variant Variable Text>
U701 = IC_24P_I2CBUS_SWITCH_TCA9548A: ASSEMBLY: <ASSEMBLY>; Variant Variable Text: <Variant Variable Text>
U702 = IC_24P_SN74LVC8T245PWR: ASSEMBLY: <ASSEMBLY>; Variant Variable Text: <Variant Variable Text>
U704 = IC_14P_LSM6DS3: ASSEMBLY: <ASSEMBLY>; Variant Variable Text: <Variant Variable Text>
C802 C810 = CAP_GRM188R61A475KE15D: ASSEMBLY: <ASSEMBLY>; Variant Variable Text: DNI
C804 C812 = CAP_GRM155R71H102KA01D: ASSEMBLY: <ASSEMBLY>; Variant Variable Text: DNI
C807 = CAP_GRM1555C1H220JA01D: ASSEMBLY: <ASSEMBLY>; Variant Variable Text: <Variant Variable Text>
CN801 = CN_6P_SIM_2P_NC_SWITCH: ASSEMBLY: <ASSEMBLY>; Variant Variable Text: <Variant Variable Text>
CN802 = MULTI_SYMBOL_104168-1620_USD: ASSEMBLY: <ASSEMBLY>; Variant Variable Text: <Variant Variable Text>
D800 D801 = DIODE_5P_ESD_RClamp0503N_3: ASSEMBLY: <ASSEMBLY>; Variant Variable Text: <Variant Variable Text>
D1202 = DIODE_8P_ESD_TPD6E004RSER: ASSEMBLY: <ASSEMBLY>; Variant Variable Text: <Variant Variable Text>
R800 R817 = RES_RK73B1ETTP153J: ASSEMBLY: <ASSEMBLY>; TOLERANCE: 5%; Variant Variable Text: DNI
R801 R810 R811 R818 R821 R822 R836 R912 R989 R1001-R1003 = RES_RK73Z1ETTP: ASSEMBLY: <ASSEMBLY>; TOLERANCE: 0%; Variant Variable Text: <Variant Variable Text>
R803 = RES_RK73H1ETTP1001F: ASSEMBLY: <ASSEMBLY>; TOLERANCE: 1%; Variant Variable Text: <Variant Variable Text>
R804 = RES_RK73B1ETTP330J: ASSEMBLY: <ASSEMBLY>; TOLERANCE: 5%; Variant Variable Text: <Variant Variable Text>
R812 = RES_MCR01MZPF1003: ASSEMBLY: <ASSEMBLY>; TOLERANCE: 1%; Variant Variable Text: DNI
R815 R820 = RES_MCR01MZPJ103: ASSEMBLY: <ASSEMBLY>; TOLERANCE: 5%; Variant Variable Text: DNI
R819 = RES_RK73H1ETTP1001F: ASSEMBLY: <ASSEMBLY>; TOLERANCE: 1%; Variant Variable Text: DNI
R823 = RES_MCR01MZPF1003: ASSEMBLY: <ASSEMBLY>; TOLERANCE: 1%; Variant Variable Text: <Variant Variable Text>
U801 = IC_8P_MEMORY_SIM_G091909: ASSEMBLY: <ASSEMBLY>; Variant Variable Text: DNI
U802 U803 U880 = IC_16P_4PDT_FSA2567: ASSEMBLY: <ASSEMBLY>; Variant Variable Text: <Variant Variable Text>
U830 = IC_5P_LDO_XC6223: ASSEMBLY: <ASSEMBLY>; Variant Variable Text: <Variant Variable Text>
CN900 CN902 = CN_2P_SINGLE_ROW: ASSEMBLY: <ASSEMBLY>; Variant Variable Text: <Variant Variable Text>
Q960 = NPN_PDTC115EM: ASSEMBLY: <ASSEMBLY>; Variant Variable Text: <Variant Variable Text>
R948 R950 R953 R966 R967 = RES_MCR01MZPJ473: ASSEMBLY: <ASSEMBLY>; TOLERANCE: 5%; Variant Variable Text: DNI
U900 U901 U904 U910 = IC_16P_TS3A5018RSVR: ASSEMBLY: <ASSEMBLY>; Variant Variable Text: <Variant Variable Text>
U903 U906 U909 = IC_28P_GPIO_EXPANDER_SX1509: ASSEMBLY: <ASSEMBLY>; Variant Variable Text: <Variant Variable Text>
U907 = IC_24P_SDIO_TXS02612ZQSR: ASSEMBLY: <ASSEMBLY>; Variant Variable Text: <Variant Variable Text>
C1020 C1030 C1040 = CAP_GRM188R61A475KE15D: ASSEMBLY: <ASSEMBLY>; Variant Variable Text: <Variant Variable Text>
C1022 C1023 C1032 C1033 C1042 C1043 = CAP_GRM188R60J106ME47D: ASSEMBLY: <ASSEMBLY>; Variant Variable Text: <Variant Variable Text>
C1035-C1037 = CAP_GRM31CR61A476ME15L: ASSEMBLY: <ASSEMBLY>; Variant Variable Text: <Variant Variable Text>
CN1000-CN1002 = CN_38P_QSPF_2110819-1: ASSEMBLY: <ASSEMBLY>; Variant Variable Text: <Variant Variable Text>
J1000-J1005 = RF_CLIP: ASSEMBLY: <ASSEMBLY>; Variant Variable Text: DNI
R1056 = RES_RK73H1ETTP6202F: ASSEMBLY: <ASSEMBLY>; TOLERANCE: 1%; Variant Variable Text: <Variant Variable Text>
RT1000 = RES_THERMISTOR: ASSEMBLY: <ASSEMBLY>; TOLERANCE: 5%; Variant Variable Text: <Variant Variable Text>

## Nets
GND: C610.1(A) C611.1(A) C613.1(A) C700.1(A) C701.2(B) C703.1(A) C704.1(A) C705.1(A) C710.1(A) C712.1(A) C714.1(A) C716.1(A) C717.1(A) C742.1(A) C743.1(A) C784.1(A) C800.2(B) C801.2(B) C802.2(B) C803.1(A) C804.1(A) C805.1(A) C806.2(B) C807.1(A) C808.2(B) C809.2(B) C810.2(B) C811.1(A) C812.1(A) C900.1(A) C901.1(A) C903.1(A) C904.2(B) C905.1(A) C907.1(A) C908.1(A) C910.1(A) C911.1(A) C912.1(A) C922.1(A) C1020.1(A) C1022.1(A) C1023.1(A) C1030.1(A) C1032.1(A) C1033.1(A) C1035.1(A) C1036.1(A) C1037.1(A) C1040.1(A) C1042.1(A) C1043.1(A) CN600.20 CN700.5 CN700.10(GND1) CN700.11(GND2) CN801.C5(GND) CN802.G1(GND) CN802.G2(GND_2) CN802.G3(GND_3) CN802.G4(GND_4) CN802.G5(GND_5) CN802.G6(GND_6) CN802.G7(GND_7) CN802.G8(GND_8) CN802.S5(GND) CN802.T6(VSS) CN902.2 CN1000.4(PIN) CN1000.21(PIN) CN1000.30(PIN) CN1000.38(PIN) CN1001.4(PIN) CN1001.21(PIN) CN1001.30(PIN) CN1001.38(PIN) CN1002.4(PIN) CN1002.21(PIN) CN1002.30(PIN) CN1002.38(PIN) D702.1(C) D702.3 D703.1(C) D703.3 D704.1(C) D704.3 D705.1(C) D705.3 D706.1(C) D706.3 D707.1(C) D707.3 D760.1(C) D800.6 D801.6 D1202.4(GND) J600.30(GND1) J600.32(GND2) J600.37(GND7) J600.48(GND4) J600.50(GND5) J600.67(GND9) J600.68(GND8) J600.69(GND3) J600.70(GND10) J600.111(GND5) J600.113(GND6) J600.125(GND9) J600.128(GND10) J600.136(GND11) J600.139(GND12) J600.167(GND3) J600.168(GND1) J600.169(GND2) J600.170(GND4) J600.171 J600.172 J600.173 J600.174 J600.175 J600.176 J600.177 J600.178 J600.179 J600.180 J600.181 J600.182 J600.183 J600.184 J600.185 J600.186 J600.187 J600.188 J600.189 J600.190 J600.191 J600.192 J600.193 J600.194 J600.195 J600.196 J600.197 J600.198 J600.199 J600.200 J600.201 J600.202 J600.203 J600.204 J600.205 J600.206 J600.207 J600.208 J600.209 J600.210 J600.211 J600.212 J600.213 J600.214 J600.215 J600.216 J600.217 J600.218 J600.219 J600.220 J600.221 J600.222 J600.223 J600.224 J600.225 J600.226 J600.227 J600.228 J600.229 J600.230 J600.231 J600.232 J600.233 J600.234 J600.G1 J600.G2 J600.G3 J600.G4 J600.G5 J600.G6 J600.G7 J600.G8 J600.G9 J600.G10 J600.G11 J600.G12 J600.G13 J600.G14 J600.G15 J600.G16 J600.G17 J600.G18 J600.G19 J600.G20 J1000.1(A) J1001.1(A) J1002.1(A) J1003.1(A) J1004.1(A) J1005.1(A) Q960.2(E) R612.1(A) R724.1(A) R725.1(A) R802.1(A) R803.1(A) R819.1(A) R833.1(A) R837.2(B) R900.1(A) R945.1(A) R946.1(A) R947.1(A) R948.1(A) R949.1(A) R950.1(A) R966.1(A) R968.1(A) RT1000.1(A) U600.3(GND1) U600.6(GND2) U601.4(GND) U700.18(GND) U701.9(GND) U701.18(A2) U701.23(A1) U701.25(EP) U702.11(GND1) U702.12(GND2) U702.13(GND3) U704.2(SDX) U704.3(SCX) U704.6(GND_1) U704.7(GND_2) U801.1(GND) U801.9(SLUG) U802.6(GND) U803.6(GND) U830.2(GND) U830.5(SLUG) U880.6(GND) U900.6(GND) U901.6(GND) U903.3(GND_2) U903.10(ADDR1) U903.17(GND) U903.26(ADDR0) U903.29(SLUG) U904.6(GND) U906.3(GND_2) U906.10(ADDR1) U906.17(GND) U906.29(SLUG) U907.C3(GND_2) U907.D3(GND) U909.3(GND_2) U909.17(GND) U909.26(ADDR0) U909.29(SLUG) U910.6(GND) ; also on sheet 1 2 3 4 5 11 12 13 14
VBATT_BB_SECONDARY: J600.16(USB_VBUS) J600.63(VBAT_BB) J600.158(VBAT_BB) ; also on sheet 2
VBATT_RF_SECONDARY: J600.61 J600.62 J600.157(VBAT_RF) ; also on sheet 2
VBUS_IOT0: C1020.2(B) C1035.2(B) R1001.1(A) ; also on sheet 5
VBUS_IOT1: C1030.2(B) C1036.2(B) R1002.1(A) ; also on sheet 5
VBUS_IOT2: C1037.2(B) C1040.2(B) R1003.1(A) ; also on sheet 5
VCC_1V8: C610.2(B) C613.2(B) C700.2(B) C701.1(A) C704.2(B) C716.2(B) C717.2(B) C742.2(B) C743.2(B) C900.2(B) C901.2(B) C903.2(B) C904.1(A) C905.2(B) C907.2(B) C908.2(B) C911.2(B) C912.2(B) C922.2(B) C1023.2(B) C1033.2(B) C1043.2(B) CN602.5 CN1000.11(PIN) CN1001.11(PIN) CN1002.11(PIN) R702.1(A) R723.2(B) R727.2(B) R749.2(B) R750.2(B) R751.2(B) R760.2(B) R761.2(B) R762.2(B) R763.2(B) R764.2(B) R765.2(B) R766.2(B) R767.2(B) R768.1(A) R769.1(A) R770.1(A) R771.1(A) R772.1(A) R773.1(A) R774.1(A) R775.1(A) R812.2(B) R823.2(B) R901.2(B) R903.1(A) R906.1(A) R907.1(A) R912.2(B) R951.2(B) R952.2(B) R953.2(B) R962.2(B) R965.2(B) R967.2(B) U600.9(VCC2) U600.12(VCC1) U601.1(VCCA) U700.11(VL) U701.21(VCC) U701.22(A0) U702.1(VCCA) U704.5(VDD_IO) U704.8(VDD) U900.14(V+) U901.14(V+) U903.4(VCC1) U903.12(VDDM) U903.18(VCC2) U904.14(V+) U906.4(VCC1) U906.12(VDDM) U906.18(VCC2) U906.26(ADDR0) U909.4(VCC1) U909.10(ADDR1) U909.12(VDDM) U909.18(VCC2) U910.14(V+) ; also on sheet 1 3 5 11 12 13 14
VCC_2V95: C803.2(B) C808.1(A) C910.2(B) CN802.T4(VDD) D1202.8(VBUS) R805.2(B) R806.2(B) R807.2(B) R808.2(B) R809.2(B) R961.2(B) U830.1(VOUT) U907.B4(VCCB0) U907.C2(VCCA) ; also on sheet 14
VCC_3V3: C806.1(A) C1022.2(B) C1032.2(B) C1042.2(B) CN1000.28(PIN) CN1000.29(PIN) CN1001.28(PIN) CN1001.29(PIN) CN1002.28(PIN) CN1002.29(PIN) R913.2(B) U830.3(CE) U830.4(VIN) ; also on sheet 1 3 5 11 12 13
VCC_3V7: C703.2(B) C705.2(B) C710.2(B) C712.2(B) C800.1(A) C805.2(B) C811.2(B) CN601.2 R815.2(B) R820.2(B) R834.1(A) U700.19(VCC) U702.23(VCCB2) U702.24(VCCB1) U802.14(VCC) U803.14(VCC) U880.14(VCC) ; also on sheet 2 3 4 11 12 14
VCC_ARD: C611.2(B) U601.5(EN) U601.8(VCCB) ; also on sheet 1
2G_TX_ON: CN600.6 U702.8(A6) ; also on sheet 14
32K_CLK: R610.2(B) ; also on sheet 14
$5I14345: J600.40(GPIO7)
$5I14346: J600.41(GPIO8)
$5I14347: J600.44(GPIO13)
$5I14351: J600.65(UIM2_DET)
$5I14352: J600.58(UIM2_CLK)
$5I14353: J600.56(UIM2_DAT)
$5I14354: J600.57(UIM2_RST)
$5I14355: J600.55(UIM2_VCC)
$5I14356: J600.21(BAT_RTC)
$5I14357: J600.24(ADC1)
$5I14358: J600.25(ADC0)
$5I14359: J600.19(MIC_P)
$5I14363: J600.20(MIC_N)
$5I14364: J600.14(HSIC_DATA)
$5I14365: J600.15(HSIC_STRB)
$5I14368: J600.17(SPKR_N)
$5I14384: J600.18(SPKR_P)
$5I14388: J600.120
$5I14390: J600.119
$5I14393: J600.143(144)
$5I14424: J600.142(143)
$5I14425: J600.141(142)
$5I14426: J600.140(141)
$5I14435: J600.124
$5I14436: J600.123
$5I14438: J600.135
$5I14439: J600.134
$5I14440: J600.133
$5I14441: J600.132
$5I14442: J600.131
$5I14443: J600.130
$5I14447: J600.129
$5I14449: J600.122
$5I14450: J600.121
$5I14452: J600.88
$5I14453: J600.89
$5I14454: J600.87
$5I14455: J600.81
$5I14456: J600.82
$5I14457: J600.84
$5I14458: J600.85
$5I14459: J600.80
$5I14460: J600.79
$5I14461: J600.78
$5I14462: J600.77
$5I14464: J600.76
$5I14465: J600.75
$5I14466: J600.74
$5I14467: J600.73
$5I14468: J600.72
$5I14469: J600.71
$5I14470: J600.86
$5I14471: J600.83
$5I14472: J600.162(SD_CLK)
$5I14475: J600.163(SD_D3)
$5I14476: J600.95(SPI2_CS0)
$5I14477: J600.94(SPI2_MISO)
$5I14478: J600.93(SPI2_MOSI)
$5I14479: J600.92(SPI2_CLK)
$5I14480: J600.91(USB_ID)
$5I14481: J600.161(SD_CMD)
$5I14482: J600.153(ANT_CTL_0)
$5I14483: J600.154(ANT_CTL_1)
$5I14489: J600.152(SAFE_PWR_REMOVE)
$5I14490: J600.151(W_DISABLE_N)
$5I14491: J600.118
$5I14492: J600.150(GPIO24)
$5I14493: J600.149(GPIO23)
$5I14494: J600.148(GPIO22)
$5I14495: J600.147(GPIO21)
$5I14496: J600.145
$5I14497: J600.144(140)
$5I14498: J600.155(ANT_CTL_2)
$5I14500: J600.156(ANT_CTL_3)
$5I14501: J600.160(RESERVED)
$5I14507: J600.98(UART2_RTS)
$5I14508: J600.97(UART2_RX)
$5I14509: J600.96(UART2_TX)
$5I14511: J600.99(UART2_CTS)
$5I14512: J600.105(GPIO33)
$5I14513: J600.90
$5I14514: J600.104(GPIO32)
$5I14517: J600.103(GPIO37)
$5I14518: J600.102(GPIO36)
$5I14519: J600.101(GPIO35)
$5I14520: J600.100(GPIO34)
$5I14521: J600.106(WWAN_LED_N)
$5I14522: J600.107(ADC2)
$5I14523: J600.108(ADC3)
$5I14524: J600.109(GPIO42)
$5I14525: J600.110(WAKE_ON_WWAN)
$5I14536: J600.114
$5I14547: J600.116
$5I15695: J600.164(SD_D2)
$5I15696: J600.165(SD_D1)
$5I15697: J600.166(SD_D0)
$5I15706: J600.146
$5I35827: J600.159(GPIO25)
$5I35930: J600.117
$5I35932: J600.115
$5I36380: J600.235(GND_SNS)
$5I36382: J600.236(RESET)
$5I36384: J600.237(TCK)
$5I36386: J600.238(TDO)
$5I36388: J600.239(TMS)
$5I36390: J600.240(TRST)
$5I36392: J600.241(TDI)
$5I36394: J600.242(RTCK)
$5I36396: J600.243(PS_HOLD)
$5I36398: J600.244(MDM_PWR_SW_ON)
$5I37787: J600.47(TP1)
$6I6748: U700.1(READY)
$6I33524: U704.10(OCS)
$6I33618: U704.11(NC)
$6I34146: CN700.1
$6I34148: CN700.6
$6I34150: CN700.4
$6I34152: CN700.9
$6I36293: U702.21(B1)
$6I36295: U702.3(A1)
$7I10569: U801.4(NC2)
$7I10571: U801.5(NC3)
$7I11771: U803.10(NC)
$7I12426: U801.2(NC1)
$7I14606: U802.10(NC)
$7I15191: U880.10(NC)
$7I16358: CN801.C6(VPP)
$7I16397: CN802.S4(RESERVED)
$7I16399: CN802.S6(VPP)
$7I16403: CN802.S8(RESERVED_2)
$12I34877: U903.11(OSCIO)
$12I34878: U906.11(OSCIO)
$12I34965: U909.11(OSCIO)
$13I34330: CN1001.33(PIN)
$13I34331: CN1001.36(PIN)
$13I34332: CN1001.35(PIN)
$13I34363: CN1002.10(PIN)
$13I34364: CN1002.9(PIN)
$13I34365: CN1002.8(PIN)
$13I34366: CN1002.7(PIN)
$13I34367: CN1002.6(PIN)
$13I34368: CN1002.5(PIN)
$13I34375: CN1001.10(PIN)
$13I34376: CN1001.9(PIN)
$13I34377: CN1001.8(PIN)
$13I34378: CN1001.7(PIN)
$13I34379: CN1001.6(PIN)
$13I34380: CN1001.5(PIN)
$13I36612: CN1001.34(PIN)
$13I36630: CN1002.36(PIN)
$13I36632: CN1002.35(PIN)
$13I36634: CN1002.34(PIN)
$13I36636: CN1002.33(PIN)
ADC0: CN1000.20(PIN) ; also on sheet 14
ADC1: CN1001.20(PIN) ; also on sheet 14
ADC2: CN1002.20(PIN) ; also on sheet 14
ADC3: R1056.1(A) RT1000.2(B) ; also on sheet 14
ANT_CTL_0: CN601.5 ; also on sheet 14
ANT_CTL_1: CN600.16 ; also on sheet 14
ANT_CTL_2: CN600.19 ; also on sheet 14
ARD_FTDI: U909.16(I/O_11) ; also on sheet 1
ARDUINO_RESET_Level shift: U903.27(I/O_0) ; also on sheet 1
ATMEGA_RESET_GPIO: U903.5(I/O_4) ; also on sheet 12
BATTCHRGR_INT_N: U906.22(I/O_15) ; also on sheet 4
BATTCHRGR_PG_N: U903.28(I/O_1) ; also on sheet 4
BATTERY_DETECT: U906.28(I/O_1) ; also on sheet 4 14
BATTGAUGE_GPIO: U903.1(I/O_2) ; also on sheet 4
BOARD_REV_RES1: R967.1(A) R968.2(B) U903.13(I/O_8)
BOARD_REV_RES2: R965.1(A) R966.2(B) U903.14(I/O_9)
CARD1_CLK: R811.2(B) U802.9(CLK1)
CARD1_DATA: D800.4 R800.1(A) R801.1(A) U802.13(DAT1)
CARD1_RESET: R810.2(B) U802.5(RST1)
CARD1_VCC: C801.1(A) C802.1(A) CN801.C1(VCC) D800.5 R800.2(B) U802.1(VSIM1)
CARD2_CLK: R813.1(A) R822.2(B) U880.8(CLK)
CARD2_DATA: D801.4 R814.1(A) R817.1(A) R818.1(A) U880.12(DAT)
CARD2_DETECT: C812.2(B) R819.2(B) R823.1(A) R835.2(B) R836.2(B) ; also on sheet 12
CARD2_RST: R816.2(B) R821.2(B) U880.4(RST)
CARD2_VCC: C809.1(A) C810.1(A) CN802.S1(VCC) D801.5 R817.2(B) U801.8(VCC) U880.16(VSIM)
CARD_DETECT_IOT0: CN1000.31(PIN) R751.1(A) U906.16(I/O_11)
CARD_DETECT_IOT1: CN1001.31(PIN) R750.1(A) U906.20(I/O_13)
CARD_DETECT_IOT2: CN1002.31(PIN) R749.1(A) U906.19(I/O_12)
CHARGER_I2C_CLK: R774.2(B) U701.17(SC7) ; also on sheet 4
CHARGER_I2C_DATA: R775.2(B) U701.16(SD7) ; also on sheet 4
CONNECT_TO_AV: R989.2(B) ; also on sheet 14
CONNECT_TO_AV_CF3: CN600.17 ; also on sheet 14
CONNECT_TO_AV_LED: U702.4(A2) U903.6(I/O_5)
D0/RX: U601.7(B1) ; also on sheet 1
D1/TX: U601.6(B2) ; also on sheet 1
EXPANION1_I2C_CLK: R768.2(B) U701.11(SC4) U903.25(SCL)
EXPANSION1_I2C_DATA: R769.2(B) U701.10(SD4) U903.24(SDA)
EXPANSION2_I2C_CLK: R770.2(B) U701.13(SC5) U906.25(SCL)
EXPANSION2_I2C_DATA: R771.2(B) U701.12(SD5) U906.24(SDA)
EXPANSION3_I2C_CLK: R772.2(B) U701.15(SC6) U909.25(SCL)
EXPANSION3_I2C_DATA: R773.2(B) U701.14(SD6) U909.24(SDA)
GPIO1/I2C1_CLK: CN602.11 U701.19(SCL) U704.13(SCL) ; also on sheet 4 11 14
GPIO3: C804.2(B) CN601.1 CN801.10(SW_B) R812.1(A) ; also on sheet 14
GPIO4: CN601.3 R836.1(A) ; also on sheet 14
GPIO5/I2C1_DATA: CN602.9 U701.20(SDA) U704.14(SDA) ; also on sheet 4 11 14
GPIO_IOT0_RESET: U909.5(I/O_4) ; also on sheet 12
GPIO_IOT1_RESET: CN602.12 U909.2(I/O_3) ; also on sheet 12
GPIO_IOT2_RESET: CN602.14 U909.1(I/O_2) ; also on sheet 12
GPIO_LOWPOWER1: CN601.19 ; also on sheet 14
GPIO_LOWPOWER2: CN601.9 ; also on sheet 14
GPIO_SCF3_RESET: U906.1(I/O_2) ; also on sheet 12 14
GPIOEXP_INT1: R903.2(B) U903.9(NINT) U906.27(I/O_0) ; also on sheet 14
GPIOEXP_INT2: CN600.12 CN900.1 ; also on sheet 14
GPIOEXP_INT3: R907.2(B) U906.21(I/O_14) U909.9(NINT)
HUB_CONNECT: U909.28(I/O_1) ; also on sheet 5
HUB_I2C_CLK: R766.1(A) U701.8(SC3) ; also on sheet 5
HUB_I2C_DATA: R767.1(A) U701.7(SD3) ; also on sheet 5
IOT0_GPIO1: CN602.13 CN802.S/W(CARD_DETECT) CN1000.24(PIN) ; also on sheet 14
IOT0_GPIO2: CN602.16 CN1000.25(PIN) ; also on sheet 14
IOT0_GPIO3: CN602.15 CN1000.26(PIN) ; also on sheet 14
IOT0_GPIO4: CN602.10 CN1000.27(PIN) ; also on sheet 14
IOT0_SCL: CN1000.23(PIN) R760.1(A) U701.2(SC0)
IOT0_SDA: CN1000.22(PIN) R761.1(A) U701.1(SD0)
IOT1_GPIO1: CN601.6 CN1001.24(PIN) ; also on sheet 14
IOT1_GPIO2: CN601.7 CN1001.25(PIN) ; also on sheet 14
IOT1_GPIO3: CN602.20 CN1001.26(PIN) ; also on sheet 14
IOT1_GPIO4: CN602.17 CN1001.27(PIN) ; also on sheet 14
IOT1_SCL: CN1001.23(PIN) R762.1(A) U701.4(SC1)
IOT1_SDA: CN1001.22(PIN) R763.1(A) U701.3(SD1)
IOT2_GPIO1: CN602.19 CN1002.24(PIN) ; also on sheet 14
IOT2_GPIO2: CN602.6 CN1002.25(PIN) ; also on sheet 14
IOT2_GPIO3: CN602.8 CN1002.26(PIN) ; also on sheet 14
IOT2_GPIO4: CN601.4 CN1002.27(PIN) ; also on sheet 14
IOT2_SCL: CN1002.23(PIN) R764.1(A) U701.6(SC2)
IOT2_SDA: CN1002.22(PIN) R765.1(A) U701.5(SD2)
LED_CARD_DETECT_IOT0: U702.5(A3) U906.2(I/O_3)
LED_CARD_DETECT_IOT1: U702.6(A4) U906.5(I/O_4)
LED_CARD_DETECT_IOT2: U702.7(A5) U906.6(I/O_5)
LED_ON: R725.2(B) U702.22(~{OE}) U903.2(I/O_3)
LOWPOWER_RESET: CN600.8 ; also on sheet 12 14
PCM_ANALOG_SELECT: U903.7(I/O_6) ; also on sheet 11
PCM_CLK: CN601.15 U910.7(COM3) ; also on sheet 14
PCM_CLK_CODEC: U910.8(NO3) ; also on sheet 11
PCM_CLK_IOT: CN1000.36(PIN) U910.9(NC3)
PCM_EXP1_ENN: R900.2(B) U909.14(I/O_9) U910.13(EN!)
PCM_EXP1_SEL: R901.1(A) U909.15(I/O_10) U910.15(IN)
PCM_IN: CN601.17 U910.10(COM4) ; also on sheet 14
PCM_IN_CODEC: U910.11(NO4) ; also on sheet 11
PCM_IN_IOT: CN1000.33(PIN) U910.12(NC4)
PCM_OUT: CN601.13 U910.5(COM2) ; also on sheet 14
PCM_OUT_CODEC: U910.4(NO2) ; also on sheet 11
PCM_OUT_IOT: CN1000.34(PIN) U910.3(NC2)
PCM_SYNC: CN601.11 U910.2(COM1) ; also on sheet 14
PCM_SYNC_CODEC: U910.1(NO1) ; also on sheet 11
PCM_SYNC_IOT: CN1000.35(PIN) U910.16(NC1)
PPS: CN601.8 CN1000.37(PIN) CN1001.37(PIN) CN1002.37(PIN) ; also on sheet 14
PWR_IND: CN600.4 ; also on sheet 14
PWR_ON: CN600.14 ; also on sheet 12 14
RESET_IN: CN600.18 ; also on sheet 12 14
RESET_IOT0: CN1000.32(PIN) ; also on sheet 12
RESET_IOT1: CN1001.32(PIN) ; also on sheet 12
RESET_IOT2: CN1002.32(PIN) ; also on sheet 12
RESET_SCF3: J600.11(RESET_IN_N) ; also on sheet 12
RS232_CTS: CN700.8 U700.8(T2OUT)
RS232_ENABLE: R727.1(A) U700.14(FORCEON) U700.20(~FORCEOFF) U909.22(I/O_15)
RS232_RTS: CN700.7 U700.9(R2IN)
RS232_RXD: CN700.2 U700.17(T1OUT)
RS232_TXD: CN700.3 U700.16(R1IN)
S_2G_TX_ON: J600.60(TXON) U702.9(A7)
S_CORRECT_INSERTION: J600.39(GND6) ; also on sheet 2
S_EXT_LNA_GPS_EN: J600.43(EXT_GPS_LNA_EN) TP612.1(A)
S_GPIO2: J600.10(GPIO2) TP610.1(A)
S_GPIO3: J600.64(UIM1_DET) R835.1(A)
S_GPIO6: J600.46(GPIO6) TP611.1(A)
S_I2C1_CLK: J600.1(I2C1_CLK) TP601.1(A)
S_I2C1_DAT: J600.66(I2C1_DAT) TP600.1(A)
S_PCM_CLK: J600.36(PCM_CLK) TP616.1(A)
S_PCM_IN: J600.34(PCM_IN) TP615.1(A)
S_PCM_OUT: J600.33(PCM_OUT) TP617.1(A)
S_PCM_SYNC: J600.35(PCM_SYNC) TP614.1(A)
S_PPS: J600.42(DR_SYNC) TP613.1(A)
S_PWR_ON: J600.59(PWR_ON_N) ; also on sheet 12
S_RF_DIV: J600.31(RF_DIV) ; also on sheet 13
S_RF_GPS: J600.38(RF_GPS) ; also on sheet 13
S_RF_MAIN: J600.49(RF_MAIN) ; also on sheet 13
S_UART1_CTS: J600.4(UART1_CTS) TP606.1(A)
S_UART1_DCD: J600.8(UART1_DCD) TP608.1(A)
S_UART1_DSR: J600.9(UART1_DSR) TP609.1(A)
S_UART1_DTR: J600.7(UART1_DTR) TP604.1(A)
S_UART1_RI: J600.2(UART1_RI) TP605.1(A)
S_UART1_RTS: J600.3(UART1_RTS) TP602.1(A)
S_UART1_RX: J600.6(UART1_RX) TP607.1(A)
S_UART1_TX: J600.5(UART1_TX) TP603.1(A)
S_UIM1_CLK: J600.27(UIM1_CLK) U880.7(CLK2)
S_UIM1_DATA: J600.28(UIM1_DAT) U880.11(DAT2)
S_UIM1_RESET: J600.29(UIM1_RST) U880.3(RST2)
S_UIM1_VCC: J600.26(UIM1_VCC) U880.15(VSIM2)
S_VGPIO: J600.45(VGPIO) TP618.1(A)
SD_CLK: CN601.12 U907.D2(CLKA) ; also on sheet 14
SD_CLK_CARD: D1202.7(IO6) R804.1(A) U907.A5(CLKB0)
SD_CLK_WIFI: CN1000.5(PIN) U907.E5(CLKB1)
SD_CMD: CN601.10 U907.C1(CMDA) ; also on sheet 14
SD_CMD_CARD: CN802.T3(CMD) D1202.6(IO5) R805.1(A) U907.A4(CMDB0)
SD_CMD_WIFI: CN1000.6(PIN) U907.E4(CMDB1)
SD_D0: CN601.20 U907.D1(DAT0A) ; also on sheet 14
SD_D0_CARD: CN802.T7(DAT0) D1202.1(IO1) R809.1(A) U907.B5(DAT0B0)
SD_D0_WIFI: CN1000.10(PIN) U907.D5(DAT0B1)
SD_D1: CN601.18 U907.E1(DAT1A) ; also on sheet 14
SD_D1_CARD: CN802.T8(DAT1) D1202.2(IO2) R808.1(A) U907.C5(DAT1B0)
SD_D1_WIFI: CN1000.9(PIN) U907.D4(DAT1B1)
SD_D2: CN601.16 U907.A1(DAT2A) ; also on sheet 14
SD_D2_CARD: CN802.T1(DAT2) D1202.3(IO3) R807.1(A) U907.B3(DAT2B0)
SD_D2_WIFI: CN1000.8(PIN) U907.E2(DAT2B1)
SD_D3: CN601.14 U907.B1(DAT3A) ; also on sheet 14
SD_D3_CARD: CN802.T2(CD/DAT3) D1202.5(IO4) R806.1(A) U907.A3(DAT3B0)
SD_D3_WIFI: CN1000.7(PIN) U907.E3(DAT3B1)
SDIO_SEL: CN902.1 Q960.1(B) R962.1(A) U903.20(I/O_13)
SDIO_SEL_LVL: Q960.3(C) R961.1(A) U907.A2(SEL)
SECOND_CARD2_CLK: U803.8(CLK) U880.9(CLK1)
SECOND_CARD2_DATA: U803.12(DAT) U880.13(DAT1)
SECOND_CARD2_RST: U803.4(RST) U880.5(RST1)
SECOND_CARD2_VCC: U803.16(VSIM) U880.1(VSIM1)
SENSOR_INT1: U704.4(INT1) U906.14(I/O_9)
SENSOR_INT2: U704.9(INT2) U906.15(I/O_10)
SPI1_CLK: U904.7(COM3) ; also on sheet 14
SPI1_CLK_IOT0: CN1000.16(PIN) U904.8(NO3)
SPI1_CLK_IOT1: CN1001.16(PIN) U904.9(NC3)
SPI1_MISO: U904.5(COM2) ; also on sheet 14
SPI1_MISO_IOT0: CN1000.17(PIN) U904.4(NO2)
SPI1_MISO_IOT1: CN1001.17(PIN) U904.3(NC2)
SPI1_MOSI: U904.10(COM4) ; also on sheet 14
SPI1_MOSI_IOT0: CN1000.18(PIN) U904.11(NO4)
SPI1_MOSI_IOT1: CN1001.18(PIN) U904.12(NC4)
SPI1_MRDY: U904.2(COM1) ; also on sheet 14
SPI1_MRDY_IOT0: CN1000.19(PIN) U904.1(NO1)
SPI1_MRDY_IOT1: CN1001.19(PIN) U904.16(NC1)
SPI2_CLK: CN1002.16(PIN) R627.1(A) ; also on sheet 14
SPI2_MISO: CN1002.17(PIN) R626.1(A) ; also on sheet 14
SPI2_MOSI: CN1002.18(PIN) R628.1(A) ; also on sheet 14
SPI2_MRDY: CN1002.19(PIN) R625.1(A) ; also on sheet 14
SPI_EXP1_ENN: R949.2(B) U903.21(I/O_14) U904.13(EN!)
SPI_EXP1_IN: R950.2(B) R951.1(A) U903.22(I/O_15) U904.15(IN)
SYSTEM_CLK: R611.2(B) ; also on sheet 11 14
SYSTEM_RESET: U701.24(RESET_N) U903.23(NRESET) U906.23(NRESET) U909.23(NRESET) ; also on sheet 5 12
UART1_CTS: CN600.5 U900.7(COM3) ; also on sheet 14
UART1_CTS_IOT0: CN1000.14(PIN) U900.8(NO3)
UART1_CTS_IOT1: CN1001.14(PIN) U900.9(NC3)
UART1_DCD: CN600.13 ; also on sheet 14
UART1_DSR: CN600.15 ; also on sheet 14
UART1_DTR: CN600.11 ; also on sheet 14
UART1_RI: CN600.1 ; also on sheet 14
UART1_RTS: CN600.3 U900.5(COM2) ; also on sheet 14
UART1_RTS_IOT0: CN1000.15(PIN) U900.4(NO2)
UART1_RTS_IOT1: CN1001.15(PIN) U900.3(NC2)
UART1_RX: CN600.9 U600.5(2A) U900.10(COM4)
UART1_RX_ARDUINO: U600.11(1B) U601.3(A2)
UART1_RX_HL_WP: U600.4(2C) ; also on sheet 14
UART1_RX_IOT0: CN1000.13(PIN) U900.11(NO4)
UART1_RX_IOT1: CN1001.13(PIN) U900.12(NC4)
UART1_TX: CN600.7 U600.2(1A) U900.2(COM1)
UART1_TX_ARDUINO: U600.8(2B) U601.2(A1)
UART1_TX_HL_WP: U600.1(1C) ; also on sheet 14
UART1_TX_IOT0: CN1000.12(PIN) U900.1(NO1)
UART1_TX_IOT1: CN1001.12(PIN) U900.16(NC1)
UART2_CTS: CN602.3 U901.7(COM3) ; also on sheet 14
UART2_CTS_DBG: U700.12(T2IN) U901.9(NC3)
UART2_CTS_IOT2: CN1002.14(PIN) U901.8(NO3)
UART2_RTS: CN602.1 U901.5(COM2) ; also on sheet 14
UART2_RTS_DBG: U700.10(R2OUT) U901.3(NC2)
UART2_RTS_IOT2: CN1002.15(PIN) U901.4(NO2)
UART2_RX: CN602.4 U901.10(COM4) ; also on sheet 14
UART2_RX_DBG: U700.13(T1IN) U901.12(NC4)
UART2_RX_IOT2: CN1002.13(PIN) U901.11(NO4)
UART2_TX: CN602.2 U901.2(COM1) ; also on sheet 14
UART2_TX_DBG: U700.15(R1OUT) U901.16(NC1)
UART2_TX_IOT2: CN1002.12(PIN) U901.1(NO1)
UART_CTRL: R612.2(B) U600.7(1S) U600.10(2S) ; also on sheet 12
UART_EXP1_ENN: R947.2(B) U900.13(EN!) U903.15(I/O_10)
UART_EXP1_IN: R948.2(B) R952.1(A) U900.15(IN) U903.16(I/O_11)
UART_EXP2_ENN: R945.2(B) U901.13(EN!) U909.13(I/O_8)
UART_EXP2_IN: R946.2(B) R953.1(A) U901.15(IN) U903.19(I/O_12)
UIM1_CLK: U802.8(CLK) ; also on sheet 14
UIM1_DATA: U802.12(DAT) ; also on sheet 14
UIM1_RESET: U802.4(RST) ; also on sheet 14
UIM1_VCC: U802.16(VSIM) ; also on sheet 14
UIM2_CLK: U803.9(CLK1) ; also on sheet 14
UIM2_DAT: U803.13(DAT1) ; also on sheet 14
UIM2_M2_S_SELECT: R820.1(A) R833.2(B) U880.2(SEL) U906.8(I/O_7)
UIM2_PWM_SELECT: C807.2(B) R815.1(A) R837.1(A) U803.2(SEL) U906.7(I/O_6)
UIM2_RST: U803.5(RST1) ; also on sheet 14
UIM2_VCC: U803.1(VSIM1) ; also on sheet 14
USB2_D+: J600.13(USB_DP) ; also on sheet 5
USB2_D-: J600.12(USB_DN) ; also on sheet 5
USB4_D+: CN1000.2(PIN) ; also on sheet 5
USB4_D-: CN1000.3(PIN) ; also on sheet 5
USB5_D+: CN1001.2(PIN) ; also on sheet 5
USB5_D-: CN1001.3(PIN) ; also on sheet 5
USB6_D+: CN1002.2(PIN) ; also on sheet 5
USB6_D-: CN1002.3(PIN) ; also on sheet 5
USB_HUB_INTN: U909.27(I/O_0) ; also on sheet 5
VGPIO: R1056.2(B) ; also on sheet 4 12 13 14
W_DISABLE_N: CN600.2 U702.10(A8) ; also on sheet 12 14
WAKE_ON_WWAN: CN600.10 ; also on sheet 14
$5N32959: J600.23(SLEEP_CLK) R610.1(A)
$5N32961: J600.22(SYSTEM_CLK) R611.1(A)
$5N34317: J600.52(SPI1_MISO) R626.2(B)
$5N34319: J600.54(SPI1_MOSI) R628.2(B)
$5N34337: J600.53(SPI1_CLK) R627.2(B)
$6N7151: C715.1(A) U700.4(C1-)
$6N15881: R719.1(A) U702.14(B8)
$6N15882: D707.2(A) R719.2(B)
$6N15883: R718.1(A) U702.15(B7)
$6N15884: D706.2(A) R718.2(B)
$6N15887: D704.2(A) R716.2(B)
$6N15889: D702.2(A) R714.2(B)
$6N15890: D703.2(A) R715.2(B)
$6N15892: R714.1(A) U702.19(B3)
$6N15893: R715.1(A) U702.18(B4)
$6N15894: R716.1(A) U702.17(B5)
$6N15895: R702.2(B) U702.2(DIR)
$6N15896: D705.2(A) R717.2(B)
$6N15897: R717.1(A) U702.16(B6)
$6N33562: R723.1(A) U704.12(CS)
$6N33602: R724.2(B) U704.1(SDO/SA0)
$6N33968: C714.2(B) U700.3(V+)
$6N33970: C784.2(B) U700.7(V-)
$6N34017: C785.2(B) U700.5(C2+)
$6N36308: D760.2(A) R780.1(A)
$7N9791: CN801.C2(RST) D800.1 R810.1(A)
$7N9792: CN801.C3(CLK) D800.3 R811.1(A)
$7N10368: CN802.S3(CLK) D801.3 R822.1(A)
$7N10375: CN802.S2(RST) D801.1 R821.1(A)
$7N10383: CN802.S7(I/O) R818.2(B)
$7N10565: R814.2(B) U801.3(DATA)
$7N11686: R813.2(B) U801.6(CLK)
$7N11690: R816.1(A) U801.7(RESET)
$7N11780: U802.15(VSIM2) U803.15(VSIM2)
$7N12301: U802.11(DAT2) U803.11(DAT2)
$7N12302: U802.3(RST2) U803.3(RST2)
$7N12303: U802.7(CLK2) U803.7(CLK2)
$7N12369: R802.2(B) R834.2(B) U802.2(SEL)
$7N12612: CN802.T5(CLK) R804.2(B)
$7N16353: CN801.C7(I/O) R801.2(B)
$12N34024: R912.1(A) R913.1(A) U907.C4(VCCB1)
$12N37935: CN900.2 R906.2(B) U906.9(NINT)
$12N38437: R989.1(A) U903.8(I/O_7)
$12N38869: TP900.1(A) U906.13(I/O_8)
$12N38882: TP901.1(A) U909.6(I/O_5)
$12N38895: TP902.1(A) U909.7(I/O_6)
$12N38908: TP903.1(A) U909.8(I/O_7)
$12N38921: TP904.1(A) U909.19(I/O_12)
$12N38934: TP905.1(A) U909.20(I/O_13)
$12N38947: TP906.1(A) U909.21(I/O_14)
$13N36670: CN1000.1(PIN) R1001.2(B)
$13N36704: CN1001.1(PIN) R1002.2(B)
$13N36738: CN1002.1(PIN) R1003.2(B)
N1603159: J600.51(SPI1_MRDY) R625.2(B)
N1626367: R780.2(B) U702.20(B2)
N1628203: C715.2(B) U700.2(C1+)
N1628303: C785.1(A) U700.6(C2-)
N1636837: CN801.9(SW_A) R803.2(B)

Not connected (* = marked no-connect by the designer): CN602 7 18; D800 2*; D801 2*; J601 1(PIN1)

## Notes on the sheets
sheet 6
- IOT#0
- IOT#1
- IOT#0
- IOT#2
- IOT#1
- IOT#2
- On Board Thermistor
sheet 7
- GPIO Expander#2
- GPIO Expander#1
- GPIO Expander#3
- I2C Address = 0111111b
- I2C Address = 0111110b
- I2C Address = 3Fh
- I2C Address = 3Eh
- I2C Address = 1110000b
- I2C Address = 70h
- SPI Expansion
- UART Expansion
- UART Expansion #1
- UART Expansion #2
- SDIO Expansion
- SD voltage select to IoT0
- PCM Expansion #1
- Default config = PCM to internal Codec
sheet 8
- UIM2
- UIM1
- ESIM
- UIM1_DETECT
- UIM2_DETECT
- SIM SELECT
- SIM SELECT
- R834 IN FOR HL8 FAST SIM
- SWITCHING, OTHERWISE LEAVE OPEN
- SD CONNECTOR
- SD detect
sheet 9
- UART (MAX 1MBPS)
- ACCELEROMETER AND GYROSCOPE
- Serial Port DB9 Female
- Port is in DCE configuration
- Pin 2 = RXD_DTE =  Mango OUT
- Pin 3 = TXD_DTE = Mango IN
- Pin 7 = RTS_DTE = Mango IN
- Pin 8 = CTS_DTE = Mango OUT
- I2C Address = 1101010b
- I2C Address = 6Ah
- default ON
- LEDs
- I2C Address = 1110001b
sheet 10
- Secondary LGA SOCKET
- J601 is CF3 socket essential that ovelap J600
- Additional Hardware Pins
- HL to ATmega through UART.
- default to WP
